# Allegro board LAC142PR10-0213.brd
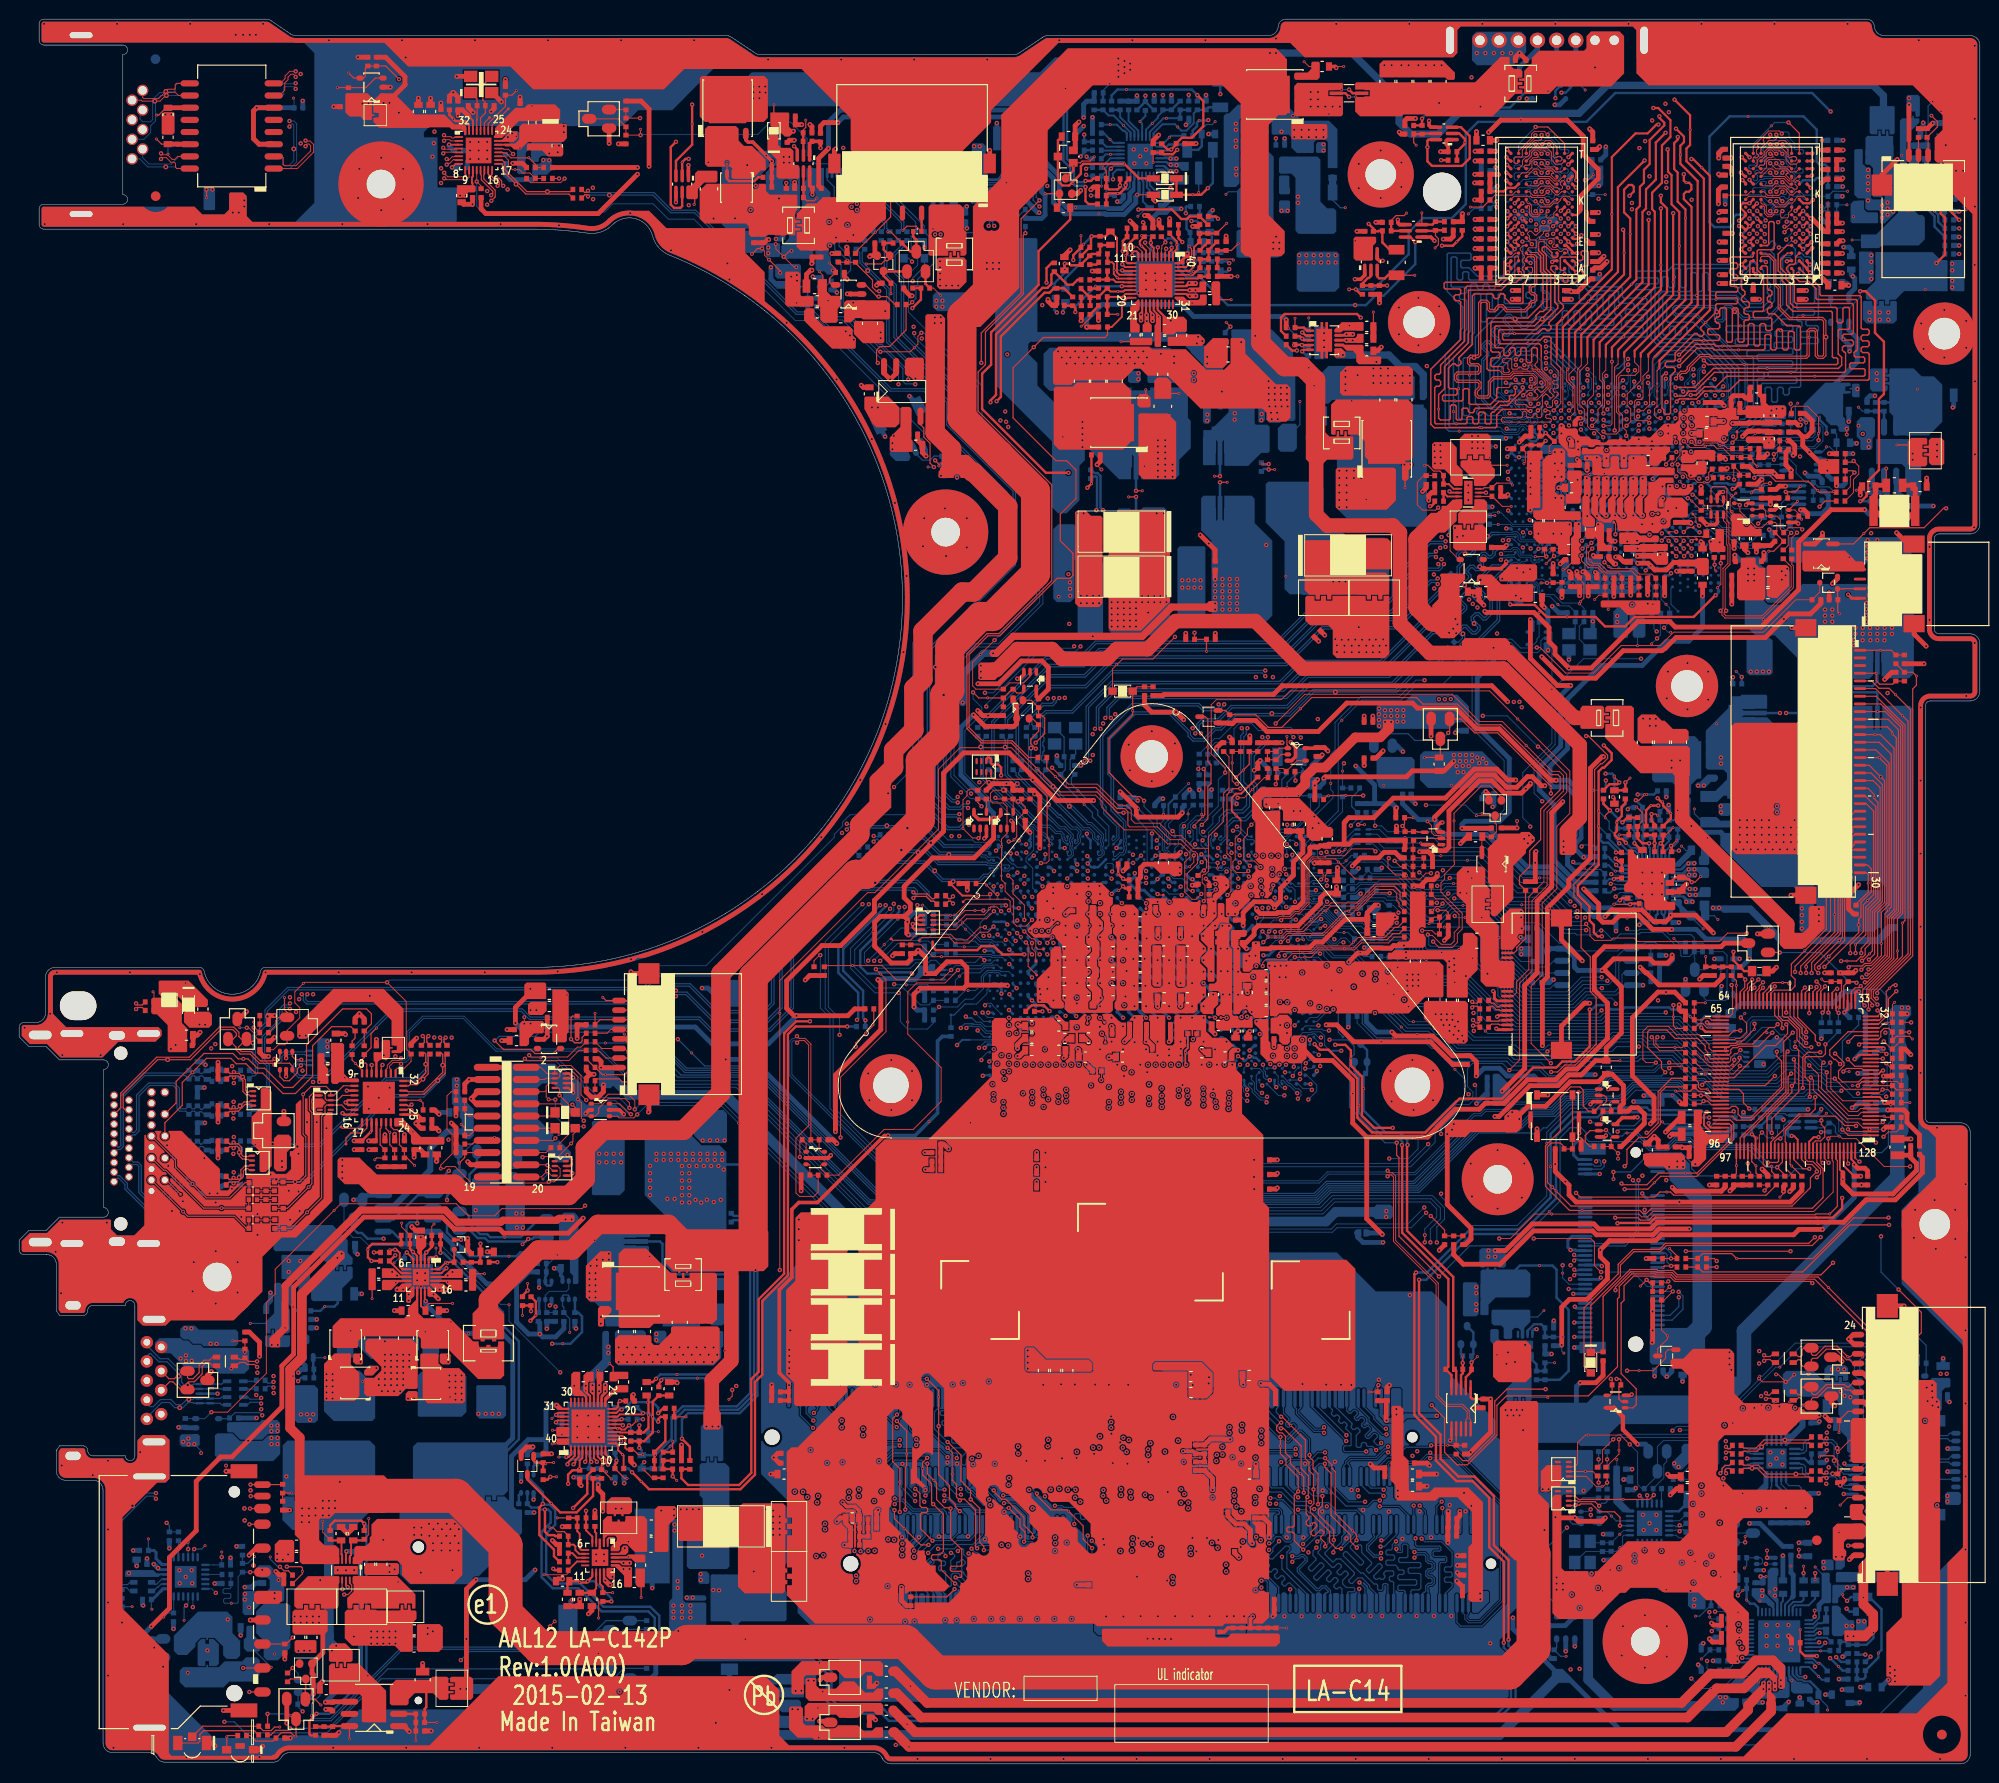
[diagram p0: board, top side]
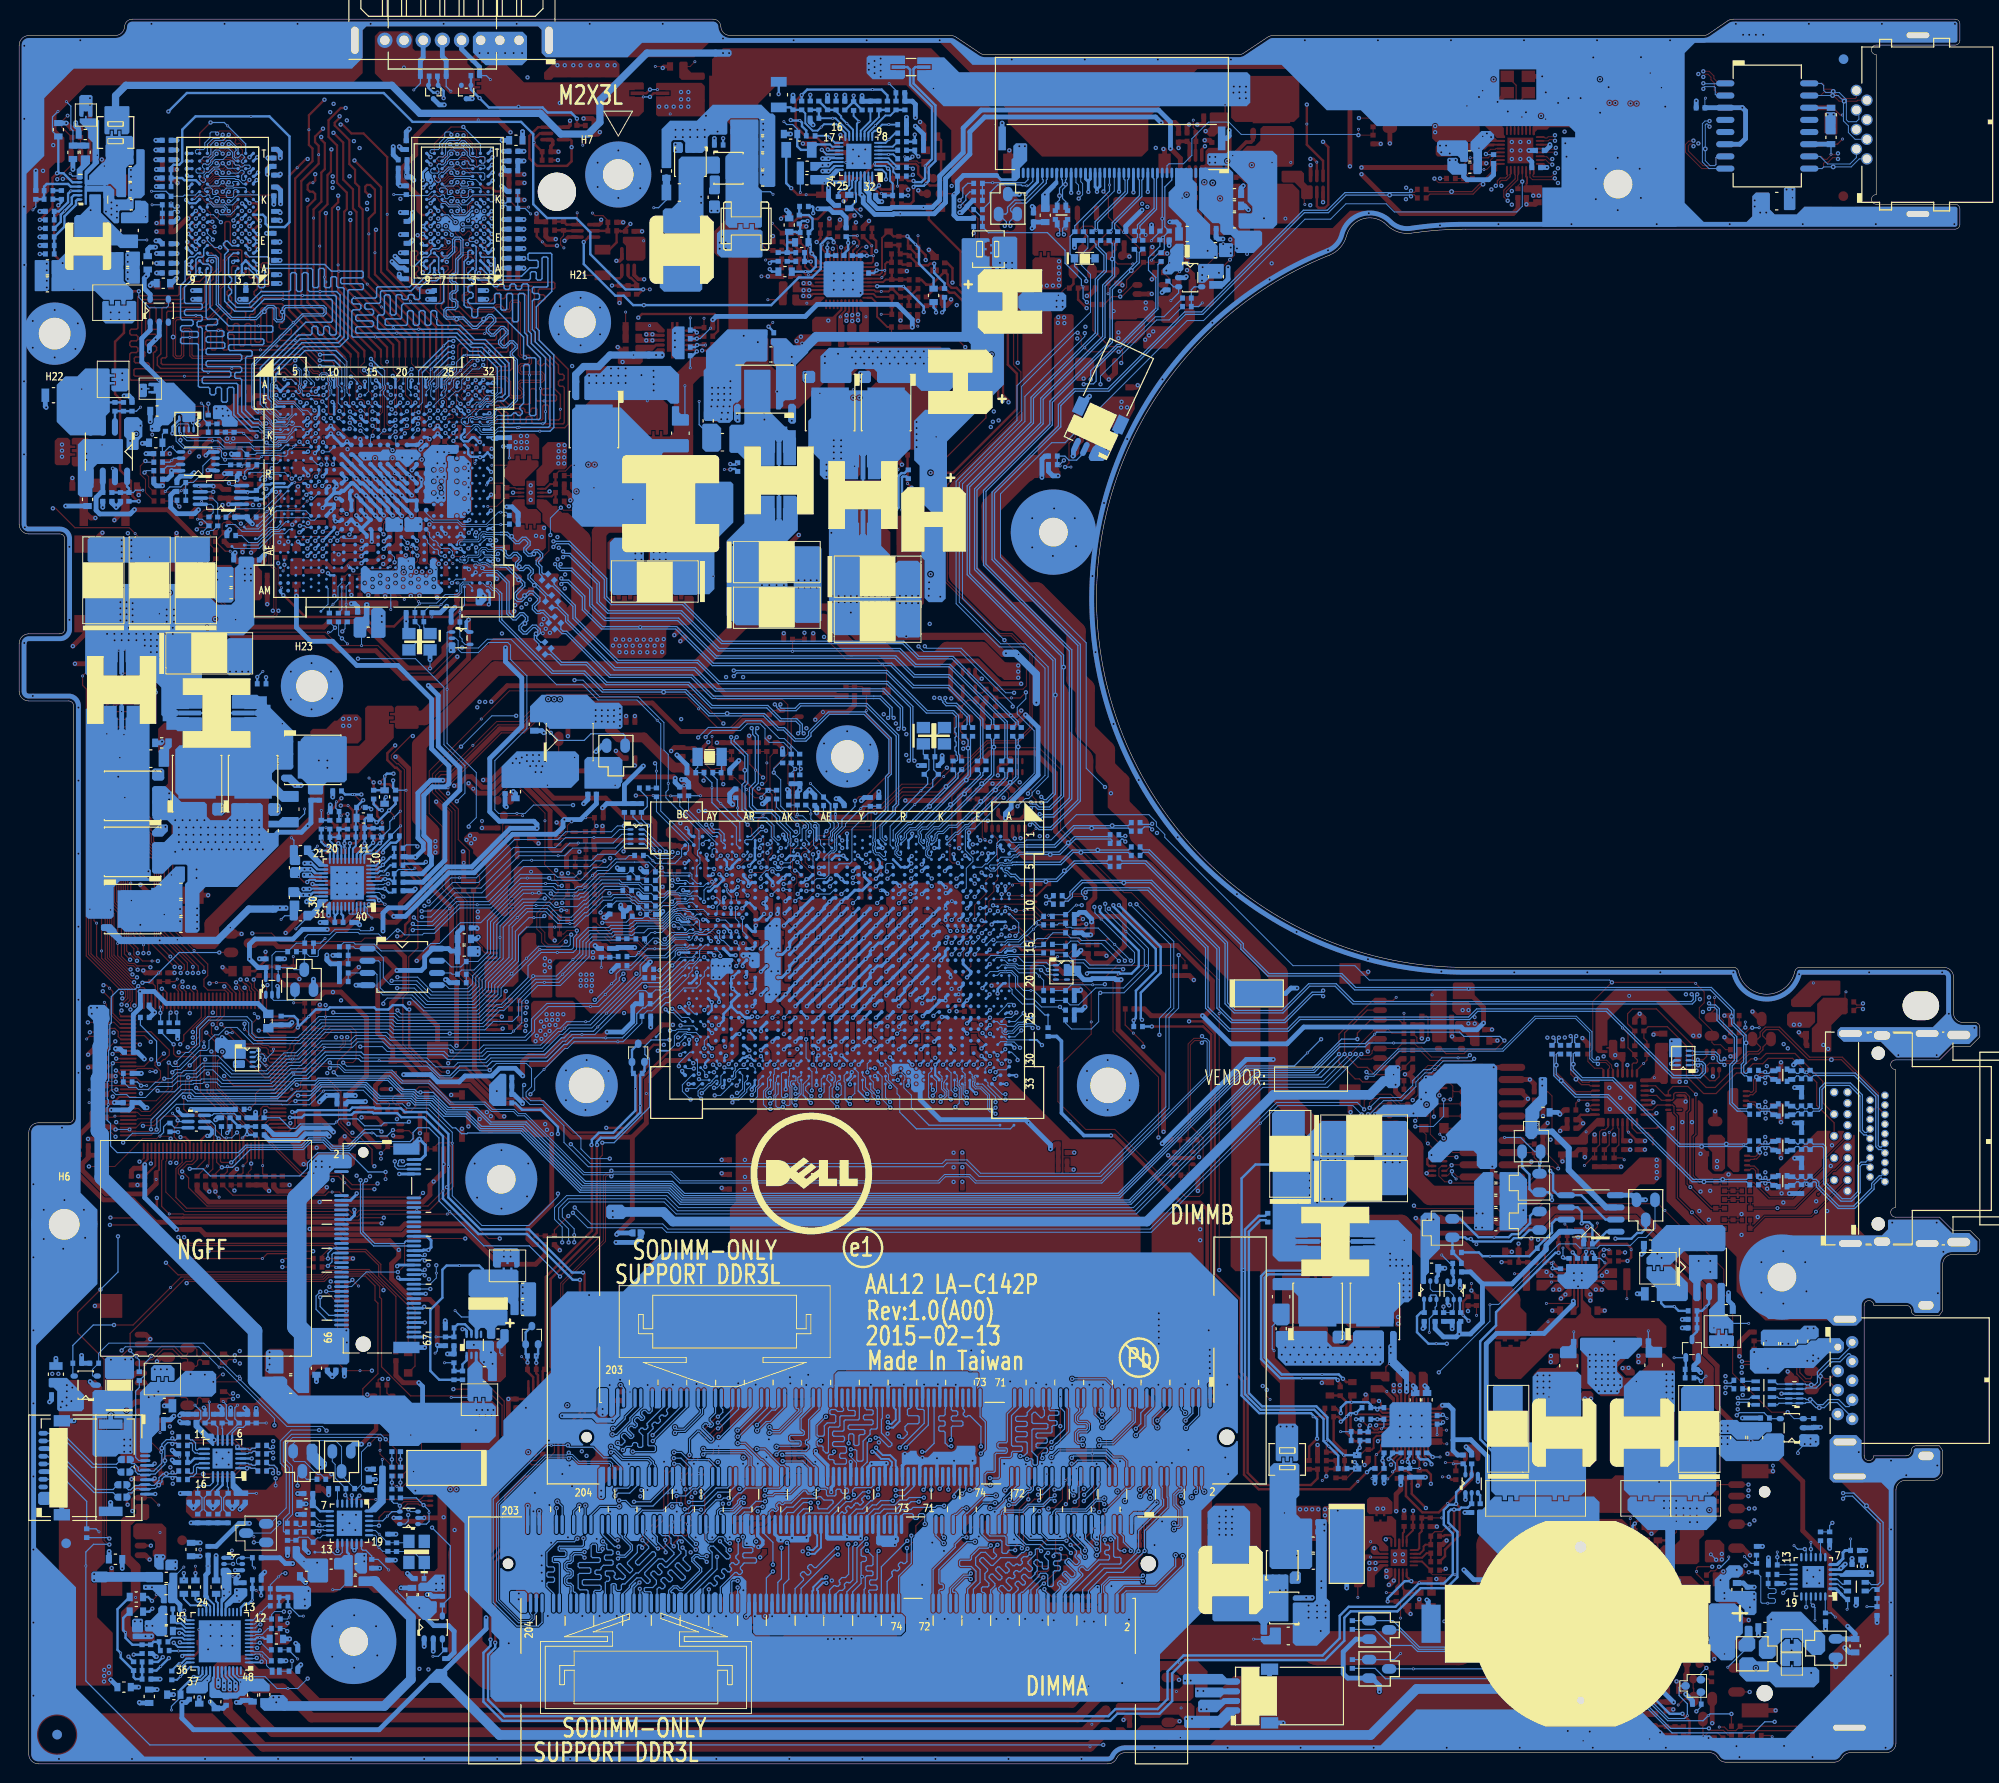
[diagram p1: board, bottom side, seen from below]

Outline 204.55 x 181.97 mm; copper layers: TOP, VCC, IN1, IN2, GND, BOTTOM. Coordinates in mm from the lower left corner of the outline.
Outline path: 0,76.82 arc(0.15,77.17) 0.5,77.32 1.75,77.32 arc(2.46,77.61) 2.75,78.32 2.75,82.07 arc(3.04,82.78) 3.75,83.07 18.81,83.07 arc(19.13,82.96) 19.3,82.67 arc(22.24,80.27) 25.18,82.67 arc(25.35,82.96) 25.67,83.07 53.65,83.07 arc(91.46,114.33) 67.86,157.35 arc(66.72,158.15) 66.07,159.38 arc(64.3,161.16) 61.87,160.51 arc(60.69,159.77) 59.3,159.65 arc(56.48,159.97) 53.65,160.07 2.58,160.07 arc(2.23,160.22) 2.08,160.57 2.08,162.17 arc(2.23,162.52) 2.58,162.67 10.81,162.67 arc(11.31,163.17) 10.81,163.67 10.81,178.27 arc(11.31,178.77) 10.81,179.27 2.58,179.27 arc(2.23,179.42) 2.08,179.77 2.08,181.47 arc(2.23,181.82) 2.58,181.97 25.74,181.97 arc(26.04,181.93) 26.31,181.8 28.29,180.43 arc(28.56,180.3) 28.86,180.26 73.75,180.26 arc(74.04,180.22) 74.3,180.09 76.8,178.43 arc(77.06,178.3) 77.35,178.26 103.75,178.26 arc(104.04,178.3) 104.3,178.43 106.8,180.09 arc(107.06,180.22) 107.35,180.26 130.35,180.26 arc(131.04,180.54) 131.35,181.21 arc(131.6,181.75) 132.15,181.97 192.75,181.97 arc(193.3,181.75) 193.55,181.21 arc(193.86,180.54) 194.55,180.26 203.55,180.26 arc(204.26,179.97) 204.55,179.26 204.55,129.28 arc(204.26,128.57) 203.55,128.28 200.3,128.28 arc(199.95,128.13) 199.8,127.78 199.8,118.36 arc(199.95,118.01) 200.3,117.86 203.55,117.86 arc(204.26,117.57) 204.55,116.86 204.55,111.86 arc(204.26,111.15) 203.55,110.86 199.38,110.86 arc(199.03,110.71) 198.88,110.36 198.88,67.36 arc(199.03,67.01) 199.38,66.86 202.55,66.86 arc(203.26,66.57) 203.55,65.86 203.55,1 arc(203.26,0.29) 202.55,0 90.96,0 arc(90.42,0.16) 90.05,0.58 arc(89.68,1.01) 89.14,1.17 28.22,1.17 arc(27.72,1.04) 27.35,0.67 arc(26.99,0.3) 26.49,0.17 15.21,0.17 arc(14.71,0.3) 14.35,0.67 arc(13.98,1.04) 13.48,1.17 9.75,1.17 arc(9.04,1.46) 8.75,2.17 8.75,28.57 arc(8.46,29.28) 7.75,29.57 4.87,29.57 arc(4.16,29.86) 3.87,30.57 3.87,32.67 4.22,33.17 6.65,33.17 arc(7,33.02) 7.15,32.67 arc(7.31,32.28) 7.7,32.12 11.07,32.12 arc(11.57,31.62) 12.07,32.12 12.07,47.82 arc(11.57,48.32) 11.07,47.82 7.7,47.82 arc(7.31,47.66) 7.15,47.27 arc(7,46.92) 6.65,46.77 4.22,46.77 3.87,47.27 3.87,52.12 arc(3.58,52.83) 2.87,53.12 0.5,53.12 arc(0.15,53.27) 0,53.62 0,54.62 1,55.62 2.8,55.62 4.2,57.02 8.8,57.02 arc(9.3,57.52) 8.8,58.02 8.8,72.42 arc(9.3,72.92) 8.8,73.42 4.2,73.42 2.8,74.82 1,74.82 0,75.82 0,76.82

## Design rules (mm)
net group APU_DP1_TXP0_VGA: nets APU_DP1_TXN0_VGA APU_DP1_TXP0_VGA
net group APU_DP1_TXP1_VGA: nets APU_DP1_TXN1_VGA APU_DP1_TXP1_VGA
net group APU_SCLK0: nets APU_SCLK0 APU_SDATA0
net group APU_VDD: nets APU_VDD_RUN_FB_L APU_VDD_SEN
net group CLK_PCIE_LAN: nets CLK_PCIE_LAN CLK_PCIE_LAN#
net group CLK_PCIE_WLAN: nets CLK_PCIE_WLAN CLK_PCIE_WLAN#
net group CLK_PEG_VGA: nets CLK_PEG_VGA CLK_PEG_VGA#
net group CPU_DPB_CTRLCLK_R: nets CPU_DPB_CTRLCLK_R CPU_DPB_CTRLDAT_R
net group CRT-HV: nets HSYNC VSYNC
net group CRT_CLK: nets CRT_CLK CRT_DATA
net group DDR3-MISC: nets MEM_MAB_EVENT# MEM_MAB_RST#
net group DDRAB_SDQS0: nets DDRAB_SDQS0 DDRAB_SDQS0#
net group DDRAB_SDQS1: nets DDRAB_SDQS1 DDRAB_SDQS1#
net group DDRAB_SDQS2: nets DDRAB_SDQS2 DDRAB_SDQS2#
net group DDRAB_SDQS3: nets DDRAB_SDQS3 DDRAB_SDQS3#
net group DDRAB_SDQS4: nets DDRAB_SDQS4 DDRAB_SDQS4#
net group DDRAB_SDQS5: nets DDRAB_SDQS5 DDRAB_SDQS5#
net group DDRAB_SDQS6: nets DDRAB_SDQS6 DDRAB_SDQS6#
net group DDRAB_SDQS7: nets DDRAB_SDQS7 DDRAB_SDQS7#
net group EC_SMB_CK1: nets EC_SMB_CK1 EC_SMB_DA1
net group EC_SMB_CK2: nets EC_SMB_CK2 EC_SMB_DA2
net group M_CLK0: nets M_CLK0 M_CLK#0
net group M_CLK1: nets M_CLK1 M_CLK#1
net group M_DQS0: nets M_DQS0 M_DQS#0
net group M_DQS1: nets M_DQS1 M_DQS#1
net group M_DQS2: nets M_DQS2 M_DQS#2
net group M_DQS3: nets M_DQS3 M_DQS#3
net group M_DQS4: nets M_DQS4 M_DQS#4
net group M_DQS5: nets M_DQS5 M_DQS#5
net group M_DQS6: nets M_DQS6 M_DQS#6
net group M_DQS7: nets M_DQS7 M_DQS#7
net group SATA_RX_P0: nets SATA_RX_N0 SATA_RX_P0
net group SATA_TX_P0: nets SATA_TX_N0 SATA_TX_P0
net group USB20_3_R: nets USB20_N3_R USB20_P3_R
net group VSUM_APU: nets VSUM+_APU VSUM-_APU
net group VSUM_VGA: nets VSUM+_VGA VSUM-_VGA
net group CRT-RGB: nets CRT_B CRT_B_2 CRT_B_C CRT_G CRT_G_2 CRT_G_C CRT_HSYNC CRT_R CRT_R_2 CRT_R_C CRT_VSYNC
net group DDR3-CLK: nets DDRA_CLK0 DDRA_CLK0# DDRA_CLK1 DDRA_CLK1# DDRB_CLK0 DDRB_CLK0# DDRB_CLK1 DDRB_CLK1#
net group DDR3-DA0: nets DDRAB_SDM0 DDRAB_SDQ0 DDRAB_SDQ1 DDRAB_SDQ2 DDRAB_SDQ3 DDRAB_SDQ4 DDRAB_SDQ5 DDRAB_SDQ6 DDRAB_SDQ7
net group DDR3-DA1: nets DDRAB_SDM1 DDRAB_SDQ8 DDRAB_SDQ9 DDRAB_SDQ10 DDRAB_SDQ11 DDRAB_SDQ12 DDRAB_SDQ13 DDRAB_SDQ14 DDRAB_SDQ15
net group DDR3-DA2: nets DDRAB_SDM2 DDRAB_SDQ16 DDRAB_SDQ17 DDRAB_SDQ18 DDRAB_SDQ19 DDRAB_SDQ20 DDRAB_SDQ21 DDRAB_SDQ22 DDRAB_SDQ23
net group DDR3-DA3: nets DDRAB_SDM3 DDRAB_SDQ24 DDRAB_SDQ25 DDRAB_SDQ26 DDRAB_SDQ27 DDRAB_SDQ28 DDRAB_SDQ29 DDRAB_SDQ30 DDRAB_SDQ31
net group DDR3-DA4: nets DDRAB_SDM4 DDRAB_SDQ32 DDRAB_SDQ33 DDRAB_SDQ34 DDRAB_SDQ35 DDRAB_SDQ36 DDRAB_SDQ37 DDRAB_SDQ38 DDRAB_SDQ39
net group DDR3-DA5: nets DDRAB_SDM5 DDRAB_SDQ40 DDRAB_SDQ41 DDRAB_SDQ42 DDRAB_SDQ43 DDRAB_SDQ44 DDRAB_SDQ45 DDRAB_SDQ46 DDRAB_SDQ47
net group DDR3-DA6: nets DDRAB_SDM6 DDRAB_SDQ48 DDRAB_SDQ49 DDRAB_SDQ50 DDRAB_SDQ51 DDRAB_SDQ52 DDRAB_SDQ53 DDRAB_SDQ54 DDRAB_SDQ55
net group DDR3-DA7: nets DDRAB_SDM7 DDRAB_SDQ56 DDRAB_SDQ57 DDRAB_SDQ58 DDRAB_SDQ59 DDRAB_SDQ60 DDRAB_SDQ61 DDRAB_SDQ62 DDRAB_SDQ63
net group DDRA-ADD/CTL: nets DDRA_ODT0 DDRA_ODT1 DDRA_SCS0# DDRA_SCS1# DDRAB_CKE0 DDRAB_CKE1 DDRAB_SBS0# DDRAB_SBS1# DDRAB_SBS2# DDRAB_SCAS# DDRAB_SMA0 DDRAB_SMA1 DDRAB_SMA2 DDRAB_SMA3 DDRAB_SMA4 DDRAB_SMA5 DDRAB_SMA6 DDRAB_SMA7 DDRAB_SMA8 DDRAB_SMA9 DDRAB_SMA10 DDRAB_SMA11 DDRAB_SMA12 DDRAB_SMA13 DDRAB_SMA14 DDRAB_SMA15 DDRAB_SRAS# DDRAB_SWE# DDRB_ODT0 DDRB_ODT1 DDRB_SCS0# DDRB_SCS1#
net group EDP: nets EDP_AUXN EDP_AUXN_C EDP_AUXP EDP_AUXP_C EDP_TXN0 EDP_TXN0_C EDP_TXN1 EDP_TXN1_C EDP_TXP0 EDP_TXP0_C EDP_TXP1 EDP_TXP1_C
net group HDA: nets APU_SPKR BEEP# HDA_BITCLK HDA_BITCLK_AUDIO HDA_RST# HDA_RST#_AUDIO HDA_SDIN0 HDA_SDOUT HDA_SDOUT_AUDIO HDA_SYNC HDA_SYNC_AUDIO N71037 N71593 PC_BEEP
net group HDMI: nets APU_DP1_TXN0 APU_DP1_TXN1 APU_DP1_TXN2 APU_DP1_TXN3 APU_DP1_TXP0 APU_DP1_TXP1 APU_DP1_TXP2 APU_DP1_TXP3 APU_HDMI_CLK APU_HDMI_CLK_C APU_HDMI_DATA APU_HDMI_DATA_C DDI1_AUX_C_DN DDI1_AUX_C_DP DP1_TXN0_C DP1_TXN0_CRT DP1_TXN1_C DP1_TXN1_CRT DP1_TXN2_C DP1_TXN3_C DP1_TXP0_C DP1_TXP0_CRT DP1_TXP1_C DP1_TXP1_CRT DP1_TXP2_C DP1_TXP3_C TMDS_L_TX0N TMDS_L_TX0P TMDS_L_TX1N TMDS_L_TX1P TMDS_L_TX2N TMDS_L_TX2P TMDS_L_TXCN TMDS_L_TXCP TMDS_TX0N TMDS_TX0P TMDS_TX1N TMDS_TX1P TMDS_TX2N TMDS_TX2P TMDS_TXCN TMDS_TXCP
net group HIGH: nets 3VS_GATE 5VS_GATE +0.95VALW_ON AGPIO66 APU_ALERT# APU_DBRDY APU_DBREQ# APU_DBREQ#_R APU_FCH_PWRGD APU_I2C0_SCL_TP APU_I2C0_SDA_TP APU_I2C1_SCL APU_I2C1_SDA APU_PCIE_RST# APU_PCIE_RST#_C APU_PCIE_RST#_R APU_PWRGD APU_PWRGD_BUF APU_RST# APU_RST#_BUF APU_SIC APU_SID APU_SVC APU_SVC_R APU_SVD APU_SVD_R APU_SVT APU_SVT_R APU_TCK APU_TDI APU_TDO APU_TEST4 APU_TEST5 APU_TEST6 APU_TEST9 APU_TEST10 APU_TEST15 APU_TEST18 APU_TEST19 APU_TEST28_H APU_TEST28_L APU_TEST31 APU_TMS APU_TRST# APU_TRST#_R APU_VDDNB_SEN DP0_HPD DP1_HPD DP_AUX_ZVSS DP_ZVSS EC_LID_OUT# EC_PME# EC_RSMRST# EC_SCI# EC_SMB_CK1_R EC_SMB_CK2_R EC_SMB_DA1_R EC_SMB_DA2_R EC_SMI# EDP_HPD ENVDD ENVDD_R GFX_SVC GFX_SVC_R GFX_SVD GFX_SVD_R GFX_SVT GFX_SVT_R H_PROCHOT# HDMI_HPLUG I2C1_SCL_TP_R I2C1_SDA_TP_R I2C_CLK I2C_CLK_TP I2C_DAT I2C_DAT_TP INVTPWM INVTPWM_R KB_RST# LAN_CLKREQ# LPC_CLK0_EC LPC_CLK1 LPC_FRAME# LPC_RST_A# ODD_EN P_ZVDDP P_ZVSS PEG_CLKREQ# PEG_CLKREQ#_G PEG_CLKREQ#_R PLT_RST# PLT_RST#_R PLT_RST_VGA# PM_SLP_S3# PXS_PWREN SATA_ZVDD SATA_ZVSS SERIRQ SUSP SUSP# SVI2_SVC SVI2_SVD SVI2_SVT SYS_RESET_L SYSON SYSON# TP_I2C_INT# TP_I2C_INT#_APU USB_OC1# USB_ZVSS USBSS_ZVDD USBSS_ZVSS VCOUT1_PH VGA_SMB_CK3 VGA_SMB_CK3_R VGA_SMB_DA3 VGA_SMB_DA3_R VR_ON WL_OFF# WL_OFF#_R WLAN_CLKREQ#
net group JTAG: nets JTAG_TCK JTAG_TDI JTAG_TDO JTAG_TMS JTAG_TRSTB
net group LAN: nets MDI0+ MDI0- MDI1+ MDI1- MDI2+ MDI2- MDI3+ MDI3- MDO0+ MDO0- MDO1+ MDO1- MDO2+ MDO2- MDO3+ MDO3-
net group PCIE-CONN: nets PCIE_ARX_DTX_N1 PCIE_ARX_DTX_P1 PCIE_ATX_C_DRX_N1 PCIE_ATX_C_DRX_P1 PCIE_ATX_DRX_N1 PCIE_ATX_DRX_P1
net group PCIE-ON BOARD: nets PCIE_ARX_DTX_N0 PCIE_ARX_DTX_N0_C PCIE_ARX_DTX_P0 PCIE_ARX_DTX_P0_C PCIE_ATX_C_DRX_N0 PCIE_ATX_C_DRX_P0 PCIE_ATX_DRX_N0 PCIE_ATX_DRX_P0 PEG_GTX_C_HRX_N0 PEG_GTX_C_HRX_N1 PEG_GTX_C_HRX_N2 PEG_GTX_C_HRX_N3 PEG_GTX_C_HRX_P0 PEG_GTX_C_HRX_P1 PEG_GTX_C_HRX_P2 PEG_GTX_C_HRX_P3 PEG_GTX_HRX_N0 PEG_GTX_HRX_N1 PEG_GTX_HRX_N2 PEG_GTX_HRX_N3 PEG_GTX_HRX_P0 PEG_GTX_HRX_P1 PEG_GTX_HRX_P2 PEG_GTX_HRX_P3 PEG_HTX_C_GRX_N0 PEG_HTX_C_GRX_N1 PEG_HTX_C_GRX_N2 PEG_HTX_C_GRX_N3 PEG_HTX_C_GRX_P0 PEG_HTX_C_GRX_P1 PEG_HTX_C_GRX_P2 PEG_HTX_C_GRX_P3 PEG_HTX_GRX_N0 PEG_HTX_GRX_N1 PEG_HTX_GRX_N2 PEG_HTX_GRX_N3 PEG_HTX_GRX_P0 PEG_HTX_GRX_P1 PEG_HTX_GRX_P2 PEG_HTX_GRX_P3
net group PLAFORMCLK-SIN: nets 32K_X1 32K_X2 48M_X1 48M_X2 RTC_CLK
net group REMOTE: nets REMOTE1+ REMOTE1- REMOTE2+ REMOTE2-
net group SATA: nets SATA_ARX_C_DTX_N0 SATA_ARX_C_DTX_P0 SATA_ARX_DTX_N0 SATA_ARX_DTX_N1 SATA_ARX_DTX_N1_C SATA_ARX_DTX_P0 SATA_ARX_DTX_P1 SATA_ARX_DTX_P1_C SATA_ARX_RC_DTX_N0 SATA_ARX_RC_DTX_N0_C SATA_ARX_RC_DTX_N0_C_R SATA_ARX_RC_DTX_P0 SATA_ARX_RC_DTX_P0_C SATA_ARX_RC_DTX_P0_C_R SATA_ATX_C_DRX_N0 SATA_ATX_C_DRX_P0 SATA_ATX_DRX_N0 SATA_ATX_DRX_N1 SATA_ATX_DRX_N1_C SATA_ATX_DRX_P0 SATA_ATX_DRX_P1 SATA_ATX_DRX_P1_C SATA_ATX_RC_DRX_N0 SATA_ATX_RC_DRX_N0_C SATA_ATX_RC_DRX_N0_C_R SATA_ATX_RC_DRX_P0 SATA_ATX_RC_DRX_P0_C SATA_ATX_RC_DRX_P0_C_R
net group SPI: nets APU_SPI_CLK APU_SPI_CLK_R APU_SPI_CS1# APU_SPI_CS1#_R APU_SPI_HOLD# APU_SPI_MISO APU_SPI_MOSI APU_SPI_TPMCS# APU_SPI_WP# EC_SPI_CLK EC_SPI_CS1# EC_SPI_MISO EC_SPI_MOSI
net group USB2.0: nets USB20_CAM_N7 USB20_CAM_N7_R USB20_CAM_P7 USB20_CAM_P7_R USB20_CR_N0 USB20_CR_N0_R USB20_CR_P0 USB20_CR_P0_R USB20_JUSB1_N6 USB20_JUSB1_N6_R USB20_JUSB1_P6 USB20_JUSB1_P6_R USB20_JUSB2_N1 USB20_JUSB2_N1_R USB20_JUSB2_P1 USB20_JUSB2_P1_R USB20_JUSB3_N2 USB20_JUSB3_N2_R USB20_JUSB3_P2 USB20_JUSB3_P2_R USB20_MINI1_N4 USB20_MINI1_P4 USB20_N3 USB20_P3 USB20_TOUCH_N5 USB20_TOUCH_P5
net group USB3.0: nets USB3RN1_JUSB1 USB3RN1_JUSB1_R USB3RP1_JUSB1 USB3RP1_JUSB1_R USB3TN1_JUSB1 USB3TN1_JUSB1_C USB3TN1_JUSB1_R USB3TP1_JUSB1 USB3TP1_JUSB1_C USB3TP1_JUSB1_R
net group VRAM-ADD/CTL: nets M_BA0 M_BA1 M_BA2 M_CAS#0 M_CAS#1 M_CKE0 M_CKE1 M_CS#0 M_CS#1 M_MA0 M_MA1 M_MA2 M_MA3 M_MA4 M_MA5 M_MA6 M_MA7 M_MA8 M_MA9 M_MA10 M_MA11 M_MA12 M_MA13 M_MA14 M_MA15 M_RAS#0 M_RAS#1 M_WE#0 M_WE#1 VRAM_ODT0 VRAM_ODT1
net group VRAM-DA0: nets M_DA0 M_DA1 M_DA2 M_DA3 M_DA4 M_DA5 M_DA6 M_DA7 M_DQM0
net group VRAM-DA1: nets M_DA8 M_DA9 M_DA10 M_DA11 M_DA12 M_DA13 M_DA14 M_DA15 M_DQM1
net group VRAM-DA2: nets M_DA16 M_DA17 M_DA18 M_DA19 M_DA20 M_DA21 M_DA22 M_DA23 M_DQM2
net group VRAM-DA3: nets M_DA24 M_DA25 M_DA26 M_DA27 M_DA28 M_DA29 M_DA30 M_DA31 M_DQM3
net group VRAM-DA4: nets M_DA32 M_DA33 M_DA34 M_DA35 M_DA36 M_DA37 M_DA38 M_DA39 M_DQM4
net group VRAM-DA5: nets M_DA40 M_DA41 M_DA42 M_DA43 M_DA44 M_DA45 M_DA46 M_DA47 M_DQM5
net group VRAM-DA6: nets M_DA48 M_DA49 M_DA50 M_DA51 M_DA52 M_DA53 M_DA54 M_DA55 M_DQM6
net group VRAM-DA7: nets M_DA56 M_DA57 M_DA58 M_DA59 M_DA60 M_DA61 M_DA62 M_DA63 M_DQM7
nets with their own width: min track width 0.102; nets A_MIC_CLK A_MIC_DATA AGPIO11 APU_FCH_POK APU_PCIE_WAKE# APU_TEST0 APU_TEST1 APU_TEST2 APU_TEST11 APU_TEST14 APU_TEST16 APU_TEST17 APU_TEST36 APU_TEST37 BT_ON# EC_ENVDD KB_DET# LPC_AD0 LPC_AD1 LPC_AD2 LPC_AD3 MIC_CLK_C ODD_DETECT# ODD_EN# PBTN_OUT# PM_SLP_S5# PXS_RST# S5_MUX_CTRL SATA_ACT# USB_OC0#
nets with their own width: min track width 0.203; nets APU_TEST410 APU_TEST411 MEM_MAB_ZVDDIO
nets with their own width: min track width 0.254; nets 0.95VS_GATE 0.775VALW_GATE AUD_HP_OUT_L_CN AUD_HP_OUT_R_CN CORE_NB_GATE ECAGND HPOUT-L HPOUT-R HPOUT-R-L HPOUT-R-R LINE1-L LINE1-R LINE1-VREFO-L LINE1-VREFO-R TEMPIN0 TEMPIN1 TEMPIN2 TEMPINRETURN VDDIO_AUDIO VGA_DMINUS VGA_DPLUS
nets with their own width: min track width 0.381; nets +MVREFDA +MVREFSA +VREF_CA +VREF_DQ ASGATE CMSRC N27266810 N28714507 N28714604 N28714637
nets with their own width: min track width 0.508; nets +0.95VALW +0.95VALWP +0.95VS +0.95VS_APU_GFX +0.95VSDGPU +0.675VSP +0.775VALW +1.5VS +1.5VSP +1.8V_ALW +1.8V_ALWP +1.8VGS +1.8VGSP +1.8VS +1.8VS_LS +1.35V +1.35V_MEM_GFX +1.35VGPUP +1.35VP +3VALW +3VALW_EC +3VALWP +3VGS +3VLP +3VS +3VS_2168_DA +3VS_APU +3VS_CAM +5V_HDD +5V_PVDD +5VA +5VALW +5VALWP +5VS +5VS_KBL +5VS_ODD +17.4V_BATT+ +17.4V_BATT++ +19V_ADPIN +19V_VIN +19VB +19VB_1.35V +19VB_1.35VGPU +19VB_3/5V +19VB_APU +19VB_GPU +19VB_VDDP_ALWP +A_VCC +APU_CORE +BIF_VDDC +CHGRTC +CODEC_AVDD2 +DP_VDDC +DP_VDDR +EC_VCCA +FBA_VREF0 +FBA_VREF1 +FBA_VREF2 +LAN_REGOUT +LAN_VDD10 +LAN_VDD33 +LAN_VDDREG +MIC2-VREFO +MPLL_PVDD +RTC_APU +RTC_APU_R +RTCBATT +RTCVCC +SPLL_PVDD +SPLL_VDDC +TPUSB_VCC +TSVDD +V18R +V_DAC +V_EC +V_TP +V_TS +V_UV4 +VBUS +VDD_CT +VDD_TOUCH +VDDCI +VDDCR_FCH_ALW +VDDD +VDDD_M +VDDD_M_M +VDDR3 +VGA_CORE GND GNDA KB_BL_PWM
nets with their own width: min track width 0.762; nets +APU_CORE_NB +MEM_VREF
nets with their own width: min track width 1.016; nets +0.675VS +3VS_TOUCH +VCC_3IN1 +VDISPLAY_VCC RING2 RING2_R SLEEVE SLEEVE_R
nets with their own width: min track width 1.524; nets +INV_PWR_SRC +LCDVDD +LCDVDD_CONN
nets with their own width: min track width 2.032; nets +3VS_WLAN_NGFF +5V_USB_PWR1 +5V_USB_PWR2

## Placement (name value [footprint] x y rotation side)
C16  .1U_0402_16V7K  [C_0402]  145.22 102.06 270 bottom
C24  1U_0402_6.3V6K  [C_0402]  143.69 97.23 270 top
C26  .1U_0402_16V7K  [C_0402]  153.6 126.87 180 top
C27  10P_0402_50V8J  [C_0402]  140.65 93.29 0 bottom
C29  1000P_0402_50V7K  [C_0402]  96.15 61.98 180 top
C30  0.1U_0402_16V7K  [C_0402]  95.23 63.75 0 top
C31  0.1U_0402_16V7K  [C_0402]  123.11 102.23 90 bottom
C32  0.1U_0402_16V7K  [C_0402]  124 102.22 90 bottom
C33  0.1U_0402_16V7K  [C_0402]  199.04 169.65 90 top
C34  0.1U_0402_16V7K  [C_0402]  198.15 169.63 90 top
C41  1U_0402_6.3V6K  [C_0402]  161.28 16.56 90 bottom
C43  1U_0402_6.3V6K  [C_0402]  176.55 23.31 270 bottom
C46  1U_0402_6.3V6K  [C_0402]  153.85 102.12 270 bottom
C62  33P_0402_50V8J  [C_0402]  166.08 22.16 270 bottom
C73  33P_0402_50V8J  [C_0402]  166.09 23.04 90 bottom
C109  0.1U_0402_16V4Z  [C_0402]  126.8 22.15 90 top
C110  0.1U_0402_16V4Z  [C_0402]  122.36 13.77 90 top
C111  0.1U_0402_16V4Z  [C_0402]  123.75 13.77 90 top
C112  1U_0402_6.3V6K  [C_0402]  126.1 27.19 270 top
C113  1U_0402_6.3V6K  [C_0402]  129.85 26.56 270 top
C114  0.1U_0402_16V4Z  [C_0402]  111.61 18.67 0 top
C115  0.1U_0402_16V4Z  [C_0402]  118.8 13.77 90 top
C116  1U_0402_6.3V6K  [C_0402]  110.55 40.31 90 top
C117  0.1U_0402_16V4Z  [C_0402]  117.02 13.77 90 top
C118  1U_0402_6.3V6K  [C_0402]  128.9 26.56 270 top
C119  0.1U_0603_25V7K  [C_0603]  13.01 13.02 270 bottom
C120  680P_0603_50V8J  [C_0603]  21.71 14.22 0 bottom
C124  1U_0402_6.3V6K  [C_0402]  151.64 19.69 180 top
C125  10U_0603_6.3V6M  [C_0603]  80.51 30.23 180 top
C126  1U_0402_6.3V6K  [C_0402]  151.64 21.72 180 top
C127  10U_0603_6.3V6M  [C_0603]  121.53 40.39 0 top
C130  0.1U_0402_16V4Z  [C_0402]  150.73 20.7 0 top
C131  4.7U_0603_6.3V6K  [C_0603]  144.65 28.96 0 top
C132  0.1U_0402_16V4Z  [C_0402]  142.47 29.97 0 top
C133  4.7U_0603_6.3V6K  [C_0603]  144.65 30.23 0 top
C134  1000P_0402_50V7K  [C_0402]  129.34 14.17 270 top
C135  4.7U_0603_6.3V6K  [C_0603]  87.62 25.65 180 top
C136  .1U_0402_16V7K  [C_0402]  149.97 24.67 180 top
C137  0.1U_0402_16V4Z  [C_0402]  87.66 24.6 180 top
C138  1U_0402_6.3V6K  [C_0402]  120.58 14.68 270 top
C139  1000P_0402_50V7K  [C_0402]  123.65 31.51 270 top
C140  .1U_0402_16V7K  [C_0402]  142.71 37.88 90 top
C141  0.01U_0402_16V7K  [C_0402]  45.57 70.1 0 top
C142  1000P_0402_50V7K  [C_0402]  88.55 24.6 0 top
C143  1000P_0402_50V7K  [C_0402]  80.3 37.9 0 top
C144  10U_0603_6.3V6M  [C_0603]  127.63 30.23 0 top
C145  4.7U_0402_6.3V6K  [C_0402]  126.61 14.17 270 top
C146  1000P_0402_50V7K  [C_0402]  87.66 23.71 180 top
C147  0.1U_0402_16V4Z  [C_0402]  131.12 14.17 270 top
C148  1000P_0402_50V7K  [C_0402]  128.45 14.17 270 top
C149  10U_0603_6.3V6M  [C_0603]  106.86 40.32 90 top
C150  10U_0603_6.3V6M  [C_0603]  129.03 40.51 180 top
C151  330U_D3_2.5VY_R6M  [C_D3]  89.49 55.75 180 top
C152  330U_D3_2.5VY_R6M  [C_D3]  89.49 46.35 180 top
C155  1U_0402_6.3V6K  [C_0402]  111.56 40.31 90 top
C156  330U_D3_2.5VY_R6M  [C_D3]  89.49 41.66 180 top
C157  15P_0402_50V8J  [C_0402]  10.72 16.4 270 bottom
C158  10U_0603_6.3V6M  [C_0603]  108.13 40.32 90 top
C159  1000P_0402_50V7K  [C_0402]  122.74 32.34 90 top
C160  15P_0402_50V8J  [C_0402]  23.3 21.77 90 bottom
C161  0.1U_0402_16V7K  [C_0402]  79.43 38.79 180 top
C162  10U_0603_6.3V6M  [C_0603]  109.4 40.32 90 top
C163  15P_0402_50V8J  [C_0402]  27.49 27.38 270 top
C164  330U_D3_2.5VY_R6M  [C_D3]  89.49 51.05 180 top
C165  10U_0603_6.3V6M  [C_0603]  121.53 38.73 0 top
C166  0.22U_0402_10V6K  [C_0402]  132.98 75.31 180 top
C167  .1U_0402_16V7K  [C_0402]  130.23 13.26 90 top
C168  15P_0402_50V8J  [C_0402]  23.55 44.12 90 top
C174  .1U_0402_16V7K  [C_0402]  122.73 30.59 90 top
C175  .1U_0402_16V7K  [C_0402]  100.01 107.18 90 bottom
C176  .1U_0402_16V7K  [C_0402]  103.69 103.68 90 bottom
C177  .1U_0402_16V7K  [C_0402]  102.55 107.18 90 bottom
C178  .1U_0402_16V7K  [C_0402]  101.15 103.68 90 bottom
C179  .1U_0402_16V7K  [C_0402]  89.46 25.53 180 top
C180  .1U_0402_16V7K  [C_0402]  81.2 38.81 180 top
C183  1000P_0402_50V7K  [C_0402]  79.4 37.9 180 top
C185  .1U_0402_16V7K  [C_0402]  104.58 103.68 90 bottom
C186  0.1U_0402_16V7K  [C_0402]  123.66 32.35 90 top
C196  .1U_0402_16V7K  [C_0402]  100.89 107.18 90 bottom
C203  1U_0402_6.3V6K  [C_0402]  143.12 83.36 90 top
C215  .1U_0402_16V7K  [C_0402]  102.04 103.68 90 bottom
C223  .1U_0402_16V7K  [C_0402]  103.43 107.18 90 bottom
C224  .1U_0402_16V7K  [C_0402]  105.97 107.18 90 bottom
C225  .1U_0402_16V7K  [C_0402]  105.09 107.18 90 bottom
C226  .1U_0402_16V7K  [C_0402]  107.12 103.68 90 bottom
C227  .1U_0402_16V7K  [C_0402]  106.23 103.68 90 bottom
C228  .1U_0402_16V7K  [C_0402]  158.17 91.11 90 top
C229  .1U_0402_16V7K  [C_0402]  157.16 91.11 90 top
C245  180P_0402_50V8J  [C_0402]  144.07 83.36 90 top
C343  330P_0402_50V7K  [C_0402]  154.57 133.1 180 top
C349  330P_0402_50V7K  [C_0402]  154.57 132.21 180 top
C431  22U_0603_6.3V6M  [C_0603]  49.78 59.94 0 bottom
C432  22U_0603_6.3V6M  [C_0603]  49.78 61.21 0 bottom
C523  4.7U_0603_6.3V6K  [C_0603]  51.17 75.44 0 top
C551  100P_0402_50V8J  [C_0402]  60.08 72.64 180 top
C553  100P_0402_50V8J  [C_0402]  60.08 71.25 180 top
C615  150P_0402_50V8J  [C_0402]  142.04 86.06 270 bottom
C620  4.7U_0603_6.3V6K  [C_0603]  191.14 157.25 270 bottom
C621  4.7U_0603_6.3V6K  [C_0603]  190.87 141.1 180 bottom
C622  4.7U_0603_6.3V6K  [C_0603]  152.29 122.25 0 top
C623  4.7U_0603_6.3V6K  [C_0603]  151.15 122.26 180 top
C635  .1U_0402_16V7K  [C_0402]  158.31 87.19 180 bottom
C636  10P_0402_50V8J  [C_0402]  157.91 81.47 0 bottom
C665  0.1U_0402_16V4Z  [C_0402]  167.77 28.57 180 bottom
C666  0.1U_0402_16V4Z  [C_0402]  169.24 21.39 0 bottom
C667  0.1U_0402_16V4Z  [C_0402]  173.88 26.01 0 bottom
C668  .1U_0402_16V7K  [C_0402]  172.26 28.7 180 bottom
C682  22P_0402_50V8J  [C_0402]  133.97 103.38 0 bottom
C686  18P_0402_50V8J  [C_0402]  131.32 103.38 180 bottom
C796  5.6P_0402_50V8D  [C_0402]  108.65 103.21 90 bottom
C797  5.6P_0402_50V8D  [C_0402]  110.13 103.21 90 bottom
C828  4.7U_0603_6.3V6K  [C_0603]  168.08 29.65 180 bottom
C831  4.7U_0603_6.3V6K  [C_0603]  168.75 20.32 0 bottom
C836  4.7U_0603_6.3V6K  [C_0603]  173.92 27.11 0 bottom
C912  150P_0402_50V8J  [C_0402]  126.42 101.55 270 bottom
C923  1U_0402_6.3V6K  [C_0402]  130.01 77.39 0 top
C934  10U_0603_6.3V6M  [C_0603]  150.68 78.93 90 top
C935  10U_0603_6.3V6M  [C_0603]  149.41 78.93 90 top
C936  1000P_0402_50V7K  [C_0402]  46.49 68.33 180 top
C939  4.7U_0603_6.3V6K  [C_0603]  152.77 102.11 270 bottom
C940  4.7U_0603_6.3V6K  [C_0603]  150.81 109.16 270 bottom
C944  .1U_0402_16V7K  [C_0402]  149.05 23.77 0 top
C945  .1U_0402_16V7K  [C_0402]  149.09 25.57 0 top
C949  10U_0603_6.3V6M  [C_0603]  130.8 78.49 180 top
C950  10U_0603_6.3V6M  [C_0603]  130.8 81.03 180 top
C951  10U_0603_6.3V6M  [C_0603]  145.66 82.99 90 top
C983  0.22U_0402_10V6K  [C_0402]  147.68 133.48 0 top
C987  0.1U_0402_16V7K  [C_0402]  147.68 132.59 0 top
C999  .1U_0402_16V7K  [C_0402]  117.4 111.43 90 top
C1000  .1U_0402_16V7K  [C_0402]  147.45 94.49 180 top
C1005  1U_0402_6.3V6K  [C_0402]  154.07 69.82 180 bottom
C1006  1U_0402_6.3V6K  [C_0402]  154.07 70.71 180 bottom
C1007  1U_0402_6.3V6K  [C_0402]  154.07 71.6 180 bottom
C1008  22U_0603_6.3V6M  [C_0603]  108.39 75.67 0 top
C1009  22U_0603_6.3V6M  [C_0603]  122.57 84.75 180 top
C1010  22U_0603_6.3V6M  [C_0603]  117.66 83.17 180 top
C1011  22U_0603_6.3V6M  [C_0603]  117.69 84.78 180 top
C1015  22U_0603_6.3V6M  [C_0603]  120.12 84.77 180 top
C1016  22U_0603_6.3V6M  [C_0603]  117.64 87.81 180 top
C1052  180P_0402_50V8J  [C_0402]  119.59 83.07 180 top
C1053  22U_0603_6.3V6M  [C_0603]  120.16 79.9 180 top
C1054  22U_0603_6.3V6M  [C_0603]  122.6 79.9 180 top
C1055  22U_0603_6.3V6M  [C_0603]  117.67 81.94 180 top
C1056  180P_0402_50V8J  [C_0402]  113.52 88.01 0 top
C1057  22U_0603_6.3V6M  [C_0603]  122.68 74.17 0 top
C1058  22U_0603_6.3V6M  [C_0603]  106.36 74.42 180 top
C1059  22U_0603_6.3V6M  [C_0603]  111.94 73.71 180 top
C1060  22U_0603_6.3V6M  [C_0603]  106.36 75.69 180 top
C1061  22U_0603_6.3V6M  [C_0603]  125.09 73.72 0 top
C1062  22U_0603_6.3V6M  [C_0603]  112.29 75.7 180 top
C1063  22U_0603_6.3V6M  [C_0603]  107.75 74.42 0 top
C1064  22U_0603_6.3V6M  [C_0603]  115.82 73.72 180 top
C1065  22U_0603_6.3V6M  [C_0603]  106.36 76.96 180 top
C1066  22U_0603_6.3V6M  [C_0603]  107.75 76.96 0 top
C1067  180P_0402_50V8J  [C_0402]  125.21 78.55 180 top
C1068  22U_0603_6.3V6M  [C_0603]  117.65 79.98 180 top
C1069  22U_0603_6.3V6M  [C_0603]  113.4 84.71 0 top
C1070  22U_0603_6.3V6M  [C_0603]  109.72 84.71 180 top
C1071  22U_0603_6.3V6M  [C_0603]  109.72 80.64 180 top
C1072  22U_0603_6.3V6M  [C_0603]  110.86 82.55 0 top
C1073  22U_0603_6.3V6M  [C_0603]  113.4 82.55 0 top
C1074  22U_0603_6.3V6M  [C_0603]  110.86 84.71 0 top
C1075  22U_0603_6.3V6M  [C_0603]  110.86 80.64 0 top
C1076  22U_0603_6.3V6M  [C_0603]  113.4 80.64 0 top
C1077  22U_0603_6.3V6M  [C_0603]  109.72 82.55 180 top
C1078  0.22U_0402_10V6K  [C_0402]  140.32 108.65 0 top
C1079  0.22U_0402_10V6K  [C_0402]  126.09 79.57 0 top
C1080  10U_0603_6.3V6M  [C_0603]  130.8 82.3 180 top
C1081  0.22U_0402_10V6K  [C_0402]  140.32 104.9 0 top
C1082  0.22U_0402_10V6K  [C_0402]  124.77 124.51 90 top
C1083  10U_0603_6.3V6M  [C_0603]  130.8 79.76 180 top
C1084  0.22U_0402_10V6K  [C_0402]  135.12 117.53 45 top
C1085  10U_0603_6.3V6M  [C_0603]  136.45 95.76 90 top
C1086  0.22U_0402_10V6K  [C_0402]  135.31 95.62 90 top
C1087  0.22U_0402_10V6K  [C_0402]  121.03 76.05 180 top
C1088  0.22U_0402_10V6K  [C_0402]  121.02 77.1 180 top
C1089  0.22U_0402_10V6K  [C_0402]  119.13 74.55 180 top
C1090  0.22U_0402_10V6K  [C_0402]  116.76 76.1 180 top
C1091  0.22U_0402_10V6K  [C_0402]  116.77 77.11 180 top
C1092  0.22U_0402_10V6K  [C_0402]  114.93 76.12 180 top
C1093  180P_0402_50V8J  [C_0402]  118.53 77.11 180 top
C1095  22U_0603_6.3V6M  [C_0603]  128.21 77.14 270 top
C1096  22U_0603_6.3V6M  [C_0603]  124.6 80.95 270 top
C1097  22U_0603_6.3V6M  [C_0603]  125.8 77 180 top
C1098  22U_0603_6.3V6M  [C_0603]  126.91 77.13 270 top
C1099  0.22U_0402_10V6K  [C_0402]  131.88 78.63 270 top
C1100  22U_0603_6.3V6M  [C_0603]  140.65 86.8 0 top
C1101  10U_0603_6.3V6M  [C_0603]  140.65 88.07 0 top
C1102  0.22U_0402_10V6K  [C_0402]  128.09 83.09 270 top
C1108  10U_0603_6.3V6M  [C_0603]  132.39 97.28 90 top
C1109  10U_0603_6.3V6M  [C_0603]  133.66 97.28 90 top
C1110  0.22U_0402_10V6K  [C_0402]  126.88 88.01 180 top
C1111  0.22U_0402_10V6K  [C_0402]  107.07 63.12 180 top
C1112  0.22U_0402_10V6K  [C_0402]  107.07 61.59 180 top
C1113  0.22U_0402_10V6K  [C_0402]  107.07 60.07 180 top
C1114  0.22U_0402_10V6K  [C_0402]  129.52 62.99 0 top
C1115  180P_0402_50V8J  [C_0402]  129.52 61.47 0 top
C1116  180P_0402_50V8J  [C_0402]  129.52 59.94 0 top
C1117  0.22U_0402_10V6K  [C_0402]  119.62 82.11 180 top
C1118  10U_0603_6.3V6M  [C_0603]  130.99 99 90 top
C1119  0.22U_0402_10V6K  [C_0402]  126.26 89.38 180 top
C1120  0.22U_0402_10V6K  [C_0402]  122.07 86.99 180 top
C1121  0.22U_0402_10V6K  [C_0402]  119.72 86.99 180 top
C1122  0.22U_0402_10V6K  [C_0402]  122.11 83.05 180 top
C1123  0.22U_0402_10V6K  [C_0402]  117.37 86.74 180 top
C1124  10U_0603_6.3V6M  [C_0603]  137.45 90.75 90 top
C1125  0.22U_0402_10V6K  [C_0402]  122.11 82.11 180 top
C1126  0.22U_0402_10V6K  [C_0402]  127.6 85.66 90 top
C1127  0.22U_0402_10V6K  [C_0402]  119.49 89.3 180 top
C1128  0.22U_0402_10V6K  [C_0402]  124.53 89.36 180 top
C1129  0.22U_0402_10V6K  [C_0402]  129.99 76.5 0 top
C1130  0.22U_0402_10V6K  [C_0402]  111.11 88.01 0 top
C1131  0.22U_0402_10V6K  [C_0402]  109.48 79.12 180 top
C1132  0.22U_0402_10V6K  [C_0402]  111.11 79.12 0 top
C1133  0.22U_0402_10V6K  [C_0402]  113.52 89.28 0 top
C1134  0.22U_0402_10V6K  [C_0402]  111.11 89.28 0 top
C1135  0.22U_0402_10V6K  [C_0402]  113.52 86.87 0 top
C1136  0.22U_0402_10V6K  [C_0402]  111.11 86.87 0 top
C1137  10U_0603_6.3V6M  [C_0603]  128.11 81.14 270 top
C1138  0.22U_0402_10V6K  [C_0402]  109.91 88.06 90 top
C1139  0.22U_0402_10V6K  [C_0402]  125.02 85.72 180 top
C1140  0.22U_0402_10V6K  [C_0402]  125.27 84.3 180 top
C1141  0.22U_0402_10V6K  [C_0402]  125.28 81.92 180 top
C1142  0.22U_0402_10V6K  [C_0402]  125.02 86.61 180 top
C1143  0.22U_0402_10V6K  [C_0402]  126.11 84.31 0 top
C1144  0.22U_0402_10V6K  [C_0402]  126.12 78.58 0 top
C1145  0.22U_0402_10V6K  [C_0402]  126.15 81 0 top
C1146  0.22U_0402_10V6K  [C_0402]  126.1 83.41 0 top
C1147  10U_0603_6.3V6M  [C_0603]  119.37 93.28 90 top
C1148  0.22U_0402_10V6K  [C_0402]  120.45 93.78 90 top
C1149  0.22U_0402_10V6K  [C_0402]  113.65 79.12 0 top
C1274  100P_0402_50V8J  [C_0402]  112.91 72.26 180 top
C1275  100P_0402_50V8J  [C_0402]  93.02 17.41 270 top
C1280  1U_0402_6.3V6K  [C_0402]  56.01 77.85 180 top
C2305  10U_0603_6.3V6M  [C_0603]  37.84 21.53 270 top
C2306  10U_0603_6.3V6M  [C_0603]  36.57 21.53 270 top
C2307  10U_0805_10V4Z  [C_0805]  40.35 12.45 0 top
C2308  10U_0603_6.3V6M  [C_0603]  40.51 13.97 0 top
C2309  0.01U_0603_25V7K  [C_0603]  34.85 23.3 90 top
C2316  10U_0603_6.3V6M  [C_0603]  29.65 22.8 180 top
C2318  10U_0603_6.3V6M  [C_0603]  29.65 21.53 180 top
C2322  0.01U_0603_25V7K  [C_0603]  33.58 23.3 90 top
C2323  10U_0603_6.3V6M  [C_0603]  30.54 13.91 270 top
C2324  10U_0603_6.3V6M  [C_0603]  29.27 13.91 270 top
C2498  0.1U_0402_10V6K  [C_0402]  152.71 38.05 270 top
C2500  2200P_0402_25V7K  [C_0402]  151.52 42.54 180 bottom
C2502  2200P_0402_25V7K  [C_0402]  151.52 41.15 180 top
C2504  2200P_0402_25V7K  [C_0402]  149.74 41.15 180 top
C2505  2200P_0402_25V7K  [C_0402]  140.47 72.01 180 bottom
C2618  4.7U_0603_6.3V6K  [C_0603]  46.28 67.94 180 bottom
C2619  4.7U_0603_6.3V6K  [C_0603]  57.91 51.69 180 bottom
C2620  4.7U_0603_6.3V6K  [C_0603]  49.78 58.67 0 bottom
C2621  4.7U_0603_6.3V6K  [C_0603]  49.78 56.13 0 bottom
C2622  4.7U_0603_6.3V6K  [C_0603]  49.78 57.4 0 bottom
C4311  0.1U_0402_16V7K  [C_0402]  89.95 159.8 270 bottom
C4312  0.1U_0402_16V7K  [C_0402]  90.84 159.8 270 bottom
C4313  0.1U_0402_16V7K  [C_0402]  91.73 159.8 270 bottom
C4314  0.1U_0402_16V7K  [C_0402]  92.61 159.8 270 bottom
C4321  0.1U_0402_16V7K  [C_0402]  87.33 158.9 270 bottom
C4322  0.1U_0402_16V7K  [C_0402]  88.21 158.88 270 bottom
C5216  470P_0402_50V7K  [C_0402]  28.52 19.69 180 top
C5217  1000P_0402_50V7K  [C_0402]  28.52 18.8 180 top
CA21  22P_0402_50V8J  [C_0402]  176.4 11.89 180 bottom
CA22  22P_0402_50V8J  [C_0402]  176.4 9.66 180 bottom
CA23  2.2U_0603_6.3V6K  [C_0603]  189.91 13.86 180 bottom
CA24  1U_0402_6.3V6K  [C_0402]  188.63 8.76 90 bottom
CA25  1U_0402_6.3V6K  [C_0402]  184.89 12.64 0 top
CA29  1000P_0402_50V7K  [C_0402]  88.7 7.16 90 top
CA30  1000P_0402_50V7K  [C_0402]  88.7 9.86 270 top
CA31  1000P_0402_50V7K  [C_0402]  88.7 3.1 90 top
CA32  1000P_0402_50V7K  [C_0402]  88.7 5.79 270 top
CA51  0.1U_0402_16V7K  [C_0402]  188.52 17.07 0 bottom
CA53  4.7U_0603_6.3V6K  [C_0603]  184.03 7.19 270 bottom
CA54  0.1U_0402_16V7K  [C_0402]  182.95 7.02 270 bottom
CA55  4.7U_0603_6.3V6K  [C_0603]  180.19 7.89 270 bottom
CA56  0.1U_0402_16V7K  [C_0402]  181.22 7.53 270 bottom
CA57  4.7U_0402_6.3V6K  [C_0402]  178.5 14.48 180 top
CA58  0.1U_0402_16V7K  [C_0402]  178.5 13.59 180 top
CA59  4.7U_0402_6.3V6K  [C_0402]  178.5 15.37 180 top
CA60  0.1U_0402_16V7K  [C_0402]  178.5 12.7 180 top
CA61  4.7U_0603_6.3V6K  [C_0603]  185.76 7.67 270 bottom
CA62  10U_0603_6.3V6M  [C_0603]  189.91 15.06 180 bottom
CA63  10U_0603_6.3V6M  [C_0603]  189.11 7.22 180 bottom
CA64  10U_0603_6.3V6M  [C_0603]  177.02 13.03 0 bottom
CA65  0.1U_0402_16V7K  [C_0402]  178.35 16.48 180 bottom
CA66  4.7U_0603_6.3V6K  [C_0603]  174.75 28.7 180 top
CA67  4.7U_0603_6.3V6K  [C_0603]  187.37 17.73 90 bottom
CA68  4.7U_0603_6.3V6K  [C_0603]  186.16 17.73 90 bottom
CA69  100P_0402_50V8J  [C_0402]  176.51 16.48 180 bottom
CA70  4.7U_0603_6.3V6K  [C_0603]  174.75 29.97 180 top
CA71  4.7U_0603_6.3V6K  [C_0603]  188.51 18.17 0 bottom
CA74  10U_0603_6.3V6M  [C_0603]  184 17.73 90 bottom
CD66  10P_0402_50V8J  [C_0402]  113.47 14.68 270 top
CD67  2.2U_0402_6.3V6M  [C_0402]  115.25 14.68 270 top
CD68  10P_0402_50V8J  [C_0402]  130.16 37.59 0 top
CD69  2.2U_0402_6.3V6M  [C_0402]  130.16 38.61 0 top
CD70  10P_0402_50V8J  [C_0402]  130.03 17.14 0 top
CD71  2.2U_0402_6.3V6M  [C_0402]  130.03 16.13 0 top
CD72  10P_0402_50V8J  [C_0402]  119.82 40.44 90 top
CD73  2.2U_0402_6.3V6M  [C_0402]  118.8 40.44 90 top
CD74  10P_0402_50V8J  [C_0402]  80.4 31.37 180 top
CD75  2.2U_0402_6.3V6M  [C_0402]  80.4 32.38 180 top
CD76  10P_0402_50V8J  [C_0402]  143.39 30.86 180 top
CD77  2.2U_0402_6.3V6M  [C_0402]  144.63 31.37 0 top
CD78  10P_0402_50V8J  [C_0402]  151.5 17.55 180 top
CD79  2.2U_0402_6.3V6M  [C_0402]  151.49 18.48 180 top
CE3  0.1U_0402_16V7K  [C_0402]  191.45 61.29 270 top
CE4  0.1U_0402_16V7K  [C_0402]  191.9 79.12 180 bottom
CE10  1000P_0402_50V7K  [C_0402]  193.55 74.23 180 bottom
CE13  1000P_0402_50V7K  [C_0402]  193.68 68.96 180 bottom
CE14  0.1U_0402_16V7K  [C_0402]  175.14 63.37 180 top
CE17  0.1U_0402_16V7K  [C_0402]  175.14 64.26 180 top
CE20  0.1U_0402_16V7K  [C_0402]  162.03 64.13 0 top
CE21  0.1U_0402_16V7K  [C_0402]  177.22 77.08 90 bottom
CE23  0.1U_0402_16V7K  [C_0402]  189.92 81.58 90 top
CE24  22P_0402_50V8J  [C_0402]  196.35 68.96 180 top
CE25  0.1U_0402_16V7K  [C_0402]  196.35 66.42 180 top
CE26  0.01U_0402_16V7K  [C_0402]  96.25 136.4 0 bottom
CE27  2.2U_0603_6.3V6K  [C_0603]  88.7 142.18 90 top
CE28  1000P_0402_50V7K  [C_0402]  92.82 138.68 0 top
CE29  2.2U_0603_6.3V6K  [C_0603]  92.83 137.54 0 top
CE30  22P_0402_50V8J  [C_0402]  148.18 86.55 0 top
CE33  0.1U_0402_16V7K  [C_0402]  196.35 71.81 180 top
CE37  0.1U_0402_16V7K  [C_0402]  191.9 77.85 180 bottom
CE39  0.1U_0402_16V7K  [C_0402]  174.76 77.6 180 top
CE40  100P_0402_50V8J  [C_0402]  185.1 60.38 90 top
CE41  1000P_0402_50V7K  [C_0402]  180.65 61.29 270 top
CE42  1000P_0402_50V7K  [C_0402]  182.43 60.38 90 top
CE43  100P_0402_50V8J  [C_0402]  179.51 83.13 270 top
CE44  4.7U_0805_10V4Z  [C_0805]  195.95 63.47 90 top
CE45  0.1U_0402_10V7K  [C_0402]  178.81 83.05 90 bottom
CE46  47P_0402_50V8J  [C_0402]  177.54 83.05 90 bottom
CE47  0.1U_0402_16V7K  [C_0402]  178.87 61.29 270 top
CE56  1U_0603_10V6K  [C_0603]  197.61 133.22 0 top
CE57  10U_0603_6.3V6M  [C_0603]  193.67 133.22 180 top
CE58  1U_0402_6.3V6K~D  [C_0402]  52.58 76.58 180 top
CH14  0.1U_0402_16V7K  [C_0402]  135.31 105.99 270 top
CH15  0.1U_0402_16V7K  [C_0402]  139.58 77.98 180 bottom
CH16  150P_0402_50V8J  [C_0402]  131.12 105.59 90 top
CH23  100P_0402_50V8J  [C_0402]  146.54 93.6 0 top
CI1  47U_0805_6.3V4Z  [C_0805]  20 42.96 90 bottom
CI2  0.1U_0402_16V7K  [C_0402]  17.33 43.87 90 bottom
CI3  0.1U_0402_10V7K  [C_0402]  24.75 39.12 0 bottom
CI4  0.1U_0402_10V7K  [C_0402]  24.75 40 0 bottom
CI5  47U_0805_6.3V4Z  [C_0805]  21.77 42.96 90 bottom
CI12  4.7U_0805_10V4Z  [C_0805]  25.2 33.19 90 bottom
CI13  0.1U_0402_16V7K  [C_0402]  21.95 36.07 0 bottom
CI14  0.1U_0402_16V7K  [C_0402]  22.03 34.09 90 bottom
CI15  0.1U_0402_16V7K  [C_0402]  17.33 36.02 270 bottom
CI18  47U_0805_6.3V4Z  [C_0805]  23.42 33.19 90 bottom
CI40  10U_0603_6.3V6M  [C_0603]  18.47 43.37 90 bottom
CI44  4.7U_0805_10V4Z  [C_0805]  200.72 39.79 90 bottom
CI45  0.1U_0402_16V7K  [C_0402]  200.26 38.48 0 bottom
CI46  0.1U_0402_16V7K  [C_0402]  198.95 41.78 180 bottom
CI47  0.1U_0402_16V7K  [C_0402]  196.26 41.78 0 bottom
CI48  150U_B15G_6.3VM_R70M  [C_B15G]  194.11 38 90 bottom
CL3  0.1U_0402_25V6  [C_0402]  52.25 172.26 90 top
CL4  4.7U_0603_6.3V6K  [C_0603]  56.13 169.48 270 top
CL5  0.1U_0402_25V6  [C_0402]  53.27 169.49 270 top
CL6  0.1U_0402_25V6  [C_0402]  45.78 172.52 90 top
CL7  0.1U_0402_25V6  [C_0402]  45.83 166.5 0 bottom
CL8  0.1U_0402_25V6  [C_0402]  45.45 168.27 0 bottom
CL9  1U_0402_6.3V4Z  [C_0402]  54.16 169.49 270 top
CL10  0.1U_0402_25V6  [C_0402]  55.05 169.49 270 top
CL12  0.1U_0402_16V7K  [C_0402]  47.3 164.29 270 top
CL13  4.7U_0603_6.3V6K  [C_0603]  46.16 164.27 270 top
CL14  10U_0603_6.3V6M  [C_0603]  42.92 171.64 90 top
CL15  0.1U_0402_10V7K  [C_0402]  44 171.63 90 top
CL16  0.1U_0402_16V7K  [C_0402]  52.81 168.78 0 bottom
CL17  4.7U_0603_6.3V6K  [C_0603]  52.51 167.7 0 bottom
CL19  4.7U_0603_6.3V6K  [C_0603]  41.65 171.64 90 top
CL30  0.1U_0402_10V7K  [C_0402]  58.68 163.32 180 top
CL31  0.1U_0402_10V7K  [C_0402]  58.68 164.21 180 top
CL33  100P_1206_2KV8J  [C_1206]  19.87 163 0 bottom
CL36  10P_0402_50V8J  [C_0402]  47.77 172.94 180 top
CL37  10P_0402_50V8J  [C_0402]  48.63 172.94 0 top
CL39  1U_0402_6.3V6K  [C_0402]  34.42 172.85 180 top
CL41  0.01U_0402_16V7K  [C_0402]  29.6 172.72 180 bottom
CLIP1  -  [EMIST-SQ-26G_1P]  75.21 80.36 180 bottom
CLIP2  EMIST-SQ-26G_1P  [EMIST_SQ-55G_1P]  160.19 30.86 0 bottom
CLIP4  EMIST-SQ-26G_1P  [EMIST_SQ-55G_1P]  66.05 22.72 270 bottom
CLRP1  SHORT PADS  [SHORTPADS]  140.14 55.37 180 bottom
CLRP2  SHORT PADS  [SHORTPADS]  193.78 27.81 0 bottom
CLRP3  SHORT PADS  [SHORTPADS]  193.78 29.11 0 bottom
CLRP4  SHORT PADS  [SHORTPADS]  193.47 30.43 0 bottom
CLRP5  SHORT PADS  [SHORTPADS]  193.43 31.74 0 bottom
CM4  22U_0603_6.3V6M~D  [C_0603]  173.54 41.97 270 bottom
CM5  0.1U_0402_10V7K~D  [C_0402]  171 63.42 90 top
CM6  22U_0603_6.3V6M~D  [C_0603]  169.86 63.31 90 top
CM7  0.1U_0402_10V7K~D  [C_0402]  171.51 41.99 270 bottom
CM8  10P_0402_50V8J  [C_0402]  171.89 63.42 90 top
CM9  2.2U_0402_6.3V6M  [C_0402]  172.4 41.99 270 bottom
CM10  10P_0402_50V8J  [C_0402]  170.62 41.99 270 bottom
CM11  2.2U_0402_6.3V6M  [C_0402]  172.78 63.42 90 top
CR1  0.1U_0402_10V7K  [C_0402]  13.33 19.87 90 bottom
CR2  4.7U_0603_6.3V6K  [C_0603]  12.25 19.9 90 bottom
CR3  1U_0402_6.3V6K  [C_0402]  12.57 22.25 0 bottom
CR4  1U_0402_6.3V6K  [C_0402]  16.1 14.82 90 bottom
CR5  5P_0402_50V8C  [C_0402]  15.67 24.19 270 bottom
CR6  5P_0402_50V8C  [C_0402]  22.08 18.81 180 bottom
CR7  0.1U_0402_10V7K  [C_0402]  24.25 17.51 90 bottom
CR8  4.7U_0603_6.3V6K  [C_0603]  25.33 17.46 90 bottom
CR9  22P_0402_50V8J  [C_0402]  21.13 20.75 0 bottom
CR11  22P_0402_50V8J  [C_0402]  27.71 12.5 270 top
CS5  1000P_0402_50V7K  [C_0402]  190.41 34.99 180 bottom
CS6  0.1U_0402_25V6K  [C_0402]  190.42 35.9 180 bottom
CS7  10U_0805_10V6K  [C_0805]  190.26 37.34 180 bottom
CS8  0.01U_0402_16V7K  [C_0402]  152.38 76.83 0 top
CS9  0.01U_0402_16V7K  [C_0402]  152.38 77.72 0 top
CS10  1000P_0402_50V7K  [C_0402]  152.79 83.57 180 top
CS11  0.1U_0402_25V6K  [C_0402]  152.79 84.45 180 top
CS12  10U_0805_10V6K  [C_0805]  152.93 85.85 180 top
CS13  0.01U_0402_16V7K  [C_0402]  152.38 79.63 0 top
CS14  0.01U_0402_16V7K  [C_0402]  152.38 78.74 0 top
CS15  1U_0402_6.3V6K  [C_0402]  154.62 96.7 90 top
CS16  0.1U_0603_50V_X7R  [C_0603]  152.65 96.71 180 top
CS27  0.1U_0402_25V6K  [C_0402]  186.81 27.29 90 bottom
CS30  0.01U_0402_16V7K  [C_0402]  186.99 29.65 0 bottom
CS31  0.01U_0402_16V7K  [C_0402]  186.99 33.21 0 bottom
CS32  0.01U_0402_16V7K  [C_0402]  186.99 30.54 0 bottom
CS33  0.01U_0402_16V7K  [C_0402]  178.73 32.32 0 bottom
CS34  0.01U_0402_16V7K  [C_0402]  186.99 34.1 0 bottom
CS35  0.01U_0402_16V7K  [C_0402]  178.73 33.21 0 bottom
CS36  0.01U_0402_16V7K  [C_0402]  178.73 31.43 0 bottom
CS37  0.01U_0402_16V7K  [C_0402]  178.73 30.54 0 bottom
CS38  0.01U_0402_16V7K  [C_0402]  186.99 29.65 0 top
CS39  0.01U_0402_16V7K  [C_0402]  186.99 30.54 0 top
CS40  0.01U_0402_16V7K  [C_0402]  186.99 34.1 0 top
CS41  0.01U_0402_16V7K  [C_0402]  186.99 33.21 0 top
CS42  0.01U_0402_16V7K  [C_0402]  186.94 36.46 270 bottom
CV1  .1U_0402_16V7K  [C_0402]  149.68 115.71 45 bottom
CV2  .1U_0402_16V7K  [C_0402]  149.06 116.34 45 bottom
CV3  .1U_0402_16V7K  [C_0402]  148.66 118.36 45 bottom
CV4  .1U_0402_16V7K  [C_0402]  148.04 118.98 45 bottom
CV5  .1U_0402_16V7K  [C_0402]  148.35 121.23 45 bottom
CV6  .1U_0402_16V7K  [C_0402]  148.98 120.59 45 bottom
CV7  .1U_0402_16V7K  [C_0402]  149.36 122.83 45 bottom
CV8  .1U_0402_16V7K  [C_0402]  148.73 123.45 45 bottom
CV9  1000P_0402_50V7K  [C_0402]  179.8 131.9 90 bottom
CV10  0.1U_0402_16V4Z  [C_0402]  182.7 132.01 90 top
CV11  0.082U_0402_16V  [C_0402]  170.74 123.67 0 top
CV15  0.68U_0402_10V  [C_0402]  165.46 123.67 0 top
CV17  8.2P_0402_50V  [C_0402]  162.42 120.06 180 bottom
CV18  8.2P_0402_50V  [C_0402]  163.26 120.07 0 bottom
CV19  10U_0603_6.3V6M  [C_0603]  168.83 118.03 180 bottom
CV20  1U_0402_6.3V4Z  [C_0402]  168.29 119.16 180 bottom
CV21  0.1U_0402_10V6K  [C_0402]  168.29 120.13 180 bottom
CV22  0.1U_0402_25V6K  [C_0402]  178.91 128.4 270 top
CV26  1U_0402_6.3V4Z  [C_0402]  173.63 125.31 270 top
CV27  10U_0603_6.3V6M  [C_0603]  175.62 125.36 90 top
CV28  0.68U_0402_10V  [C_0402]  168.98 123.66 0 top
CV29  0.68U_0402_10V  [C_0402]  167.22 123.66 0 top
CV30  10U_0603_6.3V6M  [C_0603]  171.47 126.85 270 top
CV33  1U_0402_6.3V4Z  [C_0402]  169.48 126.91 270 top
CV34  0.1U_0402_10V6K  [C_0402]  170.39 126.91 270 top
CV35  0.1U_0402_10V6K  [C_0402]  174.52 125.31 270 top
CV38  10U_0603_6.3V6M  [C_0603]  157.47 121.67 0 top
CV39  0.1U_0402_10V6K  [C_0402]  156.52 122.73 90 top
CV40  2.2U_0402_6.3V6M  [C_0402]  167.35 137.89 270 top
CV41  2.2U_0402_6.3V6M  [C_0402]  166.4 137.87 270 top
CV42  2.2U_0402_6.3V6M  [C_0402]  164.7 137.82 270 top
CV43  10U_0603_6.3V6M  [C_0603]  176.72 138.77 180 top
CV44  10U_0603_6.3V6M  [C_0603]  180.56 142.45 0 top
CV45  10U_0603_6.3V6M  [C_0603]  175.37 140.01 0 top
CV46  1U_0402_6.3V4Z  [C_0402]  155.63 122.73 90 top
CV47  2.2U_0402_6.3V6M  [C_0402]  162.32 138.81 90 top
CV48  2.2U_0402_6.3V6M  [C_0402]  176.81 141.08 90 top
CV49  0.1U_0402_10V6K  [C_0402]  178.6 141.86 0 top
CV50  0.1U_0402_10V6K  [C_0402]  175.93 141.07 90 top
CV51  0.1U_0402_10V6K  [C_0402]  178.6 140.96 0 top
CV52  0.1U_0402_10V6K  [C_0402]  168.27 137.89 270 top
CV53  0.1U_0402_10V6K  [C_0402]  169.61 137.96 270 top
CV54  10U_0603_6.3V6M  [C_0603]  158.43 130.37 270 top
CV55  10U_0603_6.3V6M  [C_0603]  159.64 130.38 270 top
CV56  1U_0402_6.3V4Z  [C_0402]  159.33 133.98 180 top
CV57  1U_0402_6.3V4Z  [C_0402]  160.71 130.12 270 top
CV58  1U_0402_6.3V4Z  [C_0402]  159.33 133.1 180 top
CV59  1U_0402_6.3V4Z  [C_0402]  159.33 132.21 180 top
CV60  1U_0402_6.3V4Z  [C_0402]  159.33 131.32 180 top
CV61  10U_0603_6.3V6M  [C_0603]  162.37 126.65 180 top
CV62  1U_0402_6.3V4Z  [C_0402]  162.38 127.71 180 top
CV63  0.1U_0402_10V6K  [C_0402]  162.5 128.59 180 top
CV64  1U_0402_6.3V4Z  [C_0402]  164.96 127.71 0 top
CV65  1U_0402_6.3V4Z  [C_0402]  164.97 128.61 0 top
CV66  1U_0402_6.3V4Z  [C_0402]  165.85 126.83 270 top
CV67  10U_0603_6.3V6M  [C_0603]  181.73 123.32 0 top
CV68  10U_0603_6.3V6M  [C_0603]  181.73 123.32 0 bottom
CV69  10U_0603_6.3V6M  [C_0603]  181.73 122.05 0 bottom
CV70  10U_0603_6.3V6M  [C_0603]  181.73 122.05 0 top
CV71  1U_0402_6.3V4Z  [C_0402]  170.42 133.4 180 top
CV72  1U_0402_6.3V4Z  [C_0402]  164.5 133.39 180 top
CV73  1U_0402_6.3V4Z  [C_0402]  166.45 133.39 180 top
CV74  1U_0402_6.3V4Z  [C_0402]  168.38 133.39 180 top
CV75  1U_0402_6.3V4Z  [C_0402]  164.31 131.64 180 top
CV76  1U_0402_6.3V4Z  [C_0402]  166.09 131.66 180 top
CV77  1U_0402_6.3V4Z  [C_0402]  167.92 131.65 180 top
CV78  1U_0402_6.3V4Z  [C_0402]  169.85 131.68 180 top
CV79  1U_0402_6.3V4Z  [C_0402]  171.36 132.61 0 top
CV80  1U_0402_6.3V4Z  [C_0402]  164.3 130.76 180 top
CV81  10U_0603_6.3V6M  [C_0603]  175.58 136.38 270 top
CV82  1U_0402_6.3V4Z  [C_0402]  174.54 136.11 270 top
CV84  10U_0603_6.3V6M  [C_0603]  182.57 138.91 270 top
CV85  1U_0402_6.3V4Z  [C_0402]  181.46 139 270 top
CV86  0.1U_0402_10V6K  [C_0402]  180.52 139 270 top
CV87  1U_0402_6.3V4Z  [C_0402]  168.3 135.53 180 top
CV88  10U_0603_6.3V6M  [C_0603]  169.23 135.94 0 top
CV89  1U_0402_6.3V4Z  [C_0402]  164.5 135.55 180 top
CV90  1U_0402_6.3V4Z  [C_0402]  166.45 135.55 180 top
CV91  10U_0603_6.3V6M  [C_0603]  182.54 139.91 90 top
CV92  1U_0402_6.3V4Z  [C_0402]  180.51 139.87 90 top
CV93  0.1U_0402_10V6K  [C_0402]  181.42 139.87 90 top
CV94  1U_0402_6.3V4Z  [C_0402]  158.62 137.55 270 top
CV95  1U_0402_6.3V4Z  [C_0402]  158.63 138.49 180 top
CV96  120P_0402_50V8J  [C_0402]  183.92 139.76 90 bottom
CV97  68P_0402_50V8J  [C_0402]  182.13 138.88 90 bottom
CV98  0.1U_0402_16V4Z  [C_0402]  179.65 136.26 180 top
CV99  0.1U_0402_16V4Z  [C_0402]  179.67 137.17 180 top
CV100  0.1U_0402_10V6K  [C_0402]  164.09 165.53 0 bottom
CV101  0.1U_0402_10V6K  [C_0402]  153.45 164.01 180 top
CV102  0.01U_0402_16V7K  [C_0402]  152.53 164.01 0 bottom
CV103  10U_0603_6.3V6M  [C_0603]  153.43 169.34 180 bottom
CV104  1U_0402_6.3V4Z  [C_0402]  153.45 157.02 180 bottom
CV105  1U_0402_6.3V4Z  [C_0402]  153.45 168.2 180 bottom
CV106  1U_0402_6.3V4Z  [C_0402]  164.16 161.8 270 bottom
CV107  1U_0402_6.3V4Z  [C_0402]  164.16 157.6 270 bottom
CV108  1U_0402_6.3V4Z  [C_0402]  153.45 160.07 180 bottom
CV109  1U_0402_6.3V4Z  [C_0402]  153.45 166.16 180 bottom
CV110  1U_0402_6.3V4Z  [C_0402]  153.45 161.08 180 bottom
CV111  0.1U_0402_10V6K  [C_0402]  153.45 159.05 180 bottom
CV112  0.1U_0402_10V6K  [C_0402]  164.16 168.37 90 bottom
CV113  0.1U_0402_10V6K  [C_0402]  164.16 158.59 90 bottom
CV114  0.1U_0402_10V6K  [C_0402]  161.24 153.67 270 bottom
CV115  0.1U_0402_10V6K  [C_0402]  153.45 167.18 180 bottom
CV116  0.1U_0402_10V6K  [C_0402]  153.45 158.04 180 bottom
CV117  0.1U_0402_10V6K  [C_0402]  153.45 161.08 180 top
CV118  10U_0603_6.3V6M  [C_0603]  153.43 169.34 180 top
CV119  1U_0402_6.3V4Z  [C_0402]  164.16 157.6 270 top
CV120  1U_0402_6.3V4Z  [C_0402]  156.42 153.67 270 bottom
CV121  1U_0402_6.3V4Z  [C_0402]  153.45 154.99 180 top
CV122  1U_0402_6.3V4Z  [C_0402]  164.16 154.89 90 top
CV123  1U_0402_6.3V4Z  [C_0402]  164.16 154.89 90 bottom
CV124  1U_0402_6.3V4Z  [C_0402]  161.24 153.67 270 top
CV125  1U_0402_6.3V4Z  [C_0402]  153.45 156 180 top
CV126  0.1U_0402_10V6K  [C_0402]  153.45 158.04 180 top
CV127  0.1U_0402_10V6K  [C_0402]  153.45 159.05 180 top
CV128  0.1U_0402_10V6K  [C_0402]  153.45 168.2 180 top
CV129  0.1U_0402_10V6K  [C_0402]  164.16 168.37 90 top
CV130  0.1U_0402_10V6K  [C_0402]  153.45 157.02 180 top
CV131  0.1U_0402_10V6K  [C_0402]  153.45 160.07 180 top
CV132  0.1U_0402_10V6K  [C_0402]  164.16 161.8 270 top
CV133  0.1U_0402_10V6K  [C_0402]  188.7 161.59 0 top
CV134  0.1U_0402_10V6K  [C_0402]  188.7 164.51 0 bottom
CV135  0.01U_0402_16V7K  [C_0402]  189.62 160.83 180 bottom
CV136  10U_0603_6.3V6M  [C_0603]  188.72 154.23 0 top
CV137  1U_0402_6.3V4Z  [C_0402]  177.98 154.4 90 top
CV138  1U_0402_6.3V4Z  [C_0402]  188.7 168.32 0 top
CV139  1U_0402_6.3V4Z  [C_0402]  188.7 165.28 0 top
CV140  1U_0402_6.3V4Z  [C_0402]  180.9 153.67 270 top
CV141  1U_0402_6.3V4Z  [C_0402]  177.98 157.73 270 top
CV142  1U_0402_6.3V4Z  [C_0402]  177.98 161.92 270 top
CV143  1U_0402_6.3V4Z  [C_0402]  177.98 166.62 270 top
CV144  0.1U_0402_10V6K  [C_0402]  188.7 167.31 0 top
CV145  0.1U_0402_10V6K  [C_0402]  188.7 166.29 0 top
CV146  0.1U_0402_10V6K  [C_0402]  188.7 156.51 0 top
CV147  0.1U_0402_10V6K  [C_0402]  185.73 153.67 270 top
CV148  0.1U_0402_10V6K  [C_0402]  177.98 158.72 90 top
CV149  0.1U_0402_10V6K  [C_0402]  177.98 167.48 90 top
CV150  0.1U_0402_10V6K  [C_0402]  188.7 157.53 0 top
CV151  10U_0603_6.3V6M  [C_0603]  188.8 154.43 0 bottom
CV152  1U_0402_6.3V4Z  [C_0402]  185.73 153.67 270 bottom
CV153  1U_0402_6.3V4Z  [C_0402]  177.98 158.72 90 bottom
CV154  1U_0402_6.3V4Z  [C_0402]  177.98 154.4 90 bottom
CV155  1U_0402_6.3V4Z  [C_0402]  188.7 167.31 0 bottom
CV156  1U_0402_6.3V4Z  [C_0402]  177.98 157.73 270 bottom
CV157  1U_0402_6.3V4Z  [C_0402]  180.9 153.67 270 bottom
CV158  1U_0402_6.3V4Z  [C_0402]  188.7 156.51 0 bottom
CV159  0.1U_0402_10V6K  [C_0402]  188.7 168.32 0 bottom
CV160  0.1U_0402_10V6K  [C_0402]  188.7 155.5 0 bottom
CV161  0.1U_0402_10V6K  [C_0402]  188.7 158.54 0 bottom
CV162  0.1U_0402_10V6K  [C_0402]  177.98 167.48 90 bottom
CV163  0.1U_0402_10V6K  [C_0402]  177.98 166.62 270 bottom
CV164  0.1U_0402_10V6K  [C_0402]  177.98 163.55 90 bottom
CV165  0.1U_0402_10V6K  [C_0402]  188.7 169.34 0 bottom
CV166  0.1U_0402_10V7K  [C_0402]  183.94 134.25 0 top
CV167  0.1U_0402_10V7K  [C_0402]  190.51 136.65 180 bottom
CV168  1U_0402_6.3V4Z  [C_0402]  161.82 135.44 270 top
CV169  10U_0603_6.3V6M  [C_0603]  191 137.79 180 bottom
CV170  0.1U_0402_10V7K  [C_0402]  190.51 133.98 180 bottom
CV171  0.1U_0402_10V6K  [C_0402]  153.45 156 180 bottom
CV172  1U_0402_6.3V4Z  [C_0402]  156.42 153.67 270 top
CV173  0.1U_0402_10V6K  [C_0402]  153.45 167.18 180 top
CV174  0.01U_0402_16V7K  [C_0402]  180.65 143.57 0 top
CV175  0.01U_0402_16V7K  [C_0402]  161.95 136.63 90 top
CV176  0.01U_0402_16V7K  [C_0402]  163.33 137.84 270 top
CV177  0.01U_0402_16V7K  [C_0402]  171.87 138.02 270 top
CV178  0.01U_0402_16V7K  [C_0402]  170.96 138.02 270 top
CV179  1U_0402_6.3V4Z  [C_0402]  164.16 158.59 90 top
CV180  0.1U_0402_10V6K  [C_0402]  188.7 158.54 0 top
CV181  1U_0402_6.3V4Z  [C_0402]  188.7 155.5 0 top
CV182  0.1U_0402_10V6K  [C_0402]  177.98 161.92 270 bottom
CV183  1U_0402_6.3V4Z  [C_0402]  188.7 157.53 0 bottom
CV184  0.1U_0402_16V7K  [C_0402]  44.63 74.94 270 bottom
CV185  0.1U_0402_16V7K  [C_0402]  43.74 74.94 270 bottom
CV186  0.1U_0402_16V7K  [C_0402]  42.86 74.94 270 bottom
CV187  0.1U_0402_16V7K  [C_0402]  41.97 74.94 270 bottom
CV188  0.1U_0402_16V7K  [C_0402]  88.53 94.74 180 bottom
CV189  0.1U_0402_16V7K  [C_0402]  88.53 95.63 180 bottom
CV190  0.1U_0402_16V7K  [C_0402]  90.73 94.49 180 bottom
CV191  0.1U_0402_16V7K  [C_0402]  90.73 93.6 180 bottom
CV192  10U_0603_6.3V6M  [C_0603]  163.92 128.09 90 top
CV193  0.1U_0402_10V6K  [C_0402]  173.66 136.11 270 top
CV194  1U_0402_6.3V4Z  [C_0402]  162.74 135.44 270 top
CV195  10U_0603_6.3V6M  [C_0603]  162.67 133.1 180 top
CV196  0.01U_0402_16V7K  [C_0402]  157.41 122.73 90 top
CV197  1U_0402_6.3V4Z  [C_0402]  159.33 134.87 180 top
CV198  1U_0402_6.3V4Z  [C_0402]  159.33 135.76 180 top
CV199  1U_0402_6.3V4Z  [C_0402]  168.14 129.04 270 top
CV200  1U_0402_6.3V4Z  [C_0402]  167.25 129.03 270 top
CV201  1U_0402_6.3V4Z  [C_0402]  172.21 131.33 180 top
CV202  1U_0402_6.3V4Z  [C_0402]  169.84 130.81 180 top
CV203  1U_0402_6.3V4Z  [C_0402]  167.9 130.78 180 top
CV204  1U_0402_6.3V4Z  [C_0402]  179.58 123.95 180 top
CV205  1U_0402_6.3V4Z  [C_0402]  172.82 130.4 270 top
CV206  1U_0402_6.3V4Z  [C_0402]  179.58 122.94 180 top
CV207  1U_0402_6.3V4Z  [C_0402]  169.47 128.68 270 top
CV208  1U_0402_6.3V4Z  [C_0402]  173.16 131.7 90 top
CV209  1U_0402_6.3V4Z  [C_0402]  170.74 128.68 270 top
CV210  1U_0402_6.3V4Z  [C_0402]  180.85 125.42 0 top
CV211  1U_0402_6.3V4Z  [C_0402]  173.73 130.4 270 top
CV212  1U_0402_6.3V4Z  [C_0402]  179.99 125.41 180 top
CV213  1U_0402_6.3V4Z  [C_0402]  179.58 121.92 180 top
CV214  1U_0402_6.3V4Z  [C_0402]  180.41 125.57 180 bottom
CV215  1U_0402_6.3V4Z  [C_0402]  181.78 124.46 0 top
CV216  1U_0402_6.3V4Z  [C_0402]  181.25 125.58 0 bottom
CV217  1U_0402_6.3V4Z  [C_0402]  181.78 124.46 0 bottom
CV218  1U_0402_6.3V4Z  [C_0402]  166.08 130.79 180 top
CV357  1P_0402_50V8J  [C_0402]  21.66 68.64 180 top
CV358  1P_0402_50V8J  [C_0402]  21.66 67.75 180 top
CV359  1P_0402_50V8J  [C_0402]  21.66 72.33 180 top
CV360  1P_0402_50V8J  [C_0402]  21.66 71.44 180 top
CV361  1P_0402_50V8J  [C_0402]  21.66 64.96 180 top
CV362  1P_0402_50V8J  [C_0402]  21.66 64.07 180 top
CV363  1P_0402_50V8J  [C_0402]  21.6 61.28 180 top
CV364  1P_0402_50V8J  [C_0402]  21.6 60.39 180 top
CVT90  0.1U_0402_10V7K  [C_0402]  179.79 135.34 180 top
CX1  0.1U_0402_10V7K  [C_0402]  98.74 160.83 90 bottom
CX2  0.1U_0402_10V7K  [C_0402]  80.59 160.13 180 bottom
CX3  10U_0805_10V6K  [C_0805]  80.59 157.87 180 bottom
CX5  0.1U_0603_25V7K  [C_0603]  78.47 163.77 180 bottom
CX6  10U_0603_6.3V6M  [C_0603]  78.47 162.5 180 bottom
CX7  4.7U_0805_10V4Z  [C_0805]  79.7 155.96 270 bottom
CX8  4.7U_0805_10V4Z  [C_0805]  81.84 159.56 0 bottom
CX11  0.1U_0402_10V7K  [C_0402]  80.59 159.25 180 bottom
CX12  0.1U_0402_10V7K  [C_0402]  23.09 68.64 0 bottom
CX13  0.1U_0402_10V7K  [C_0402]  23.09 67.75 0 bottom
CX14  0.1U_0402_10V7K  [C_0402]  23.09 72.33 0 bottom
CX15  0.1U_0402_10V7K  [C_0402]  23.09 71.44 0 bottom
CX16  0.1U_0402_10V7K  [C_0402]  23.09 64.96 0 bottom
CX17  0.1U_0402_10V7K  [C_0402]  23.09 64.07 0 bottom
CX18  0.1U_0402_10V7K  [C_0402]  23.09 61.28 0 bottom
CX19  0.1U_0402_10V7K  [C_0402]  23.09 60.39 0 bottom
CX20  220P_0402_50V8J  [C_0402]  25.1 78.04 0 top
CX21  0.1U_0402_16V7K  [C_0402]  17.13 74.93 0 top
CX22  10U_0603_6.3V6M  [C_0603]  16.74 76 0 top
CX23  3.3P_0402_50V8C  [C_0402]  18.6 68.63 90 bottom
CX24  3.3P_0402_50V8C  [C_0402]  18.6 67.77 270 bottom
CX25  3.3P_0402_50V8C  [C_0402]  18.6 72.31 90 bottom
